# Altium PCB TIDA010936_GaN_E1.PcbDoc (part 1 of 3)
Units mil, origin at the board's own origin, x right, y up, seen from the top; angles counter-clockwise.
Board outline 2755.91 x 2708.83 mil, 4 copper layers (Top Layer, POWER, GND, Bottom Layer), stack 64.224 mil thick; 223 components, 99 nets, 571 pads, 439 vias.
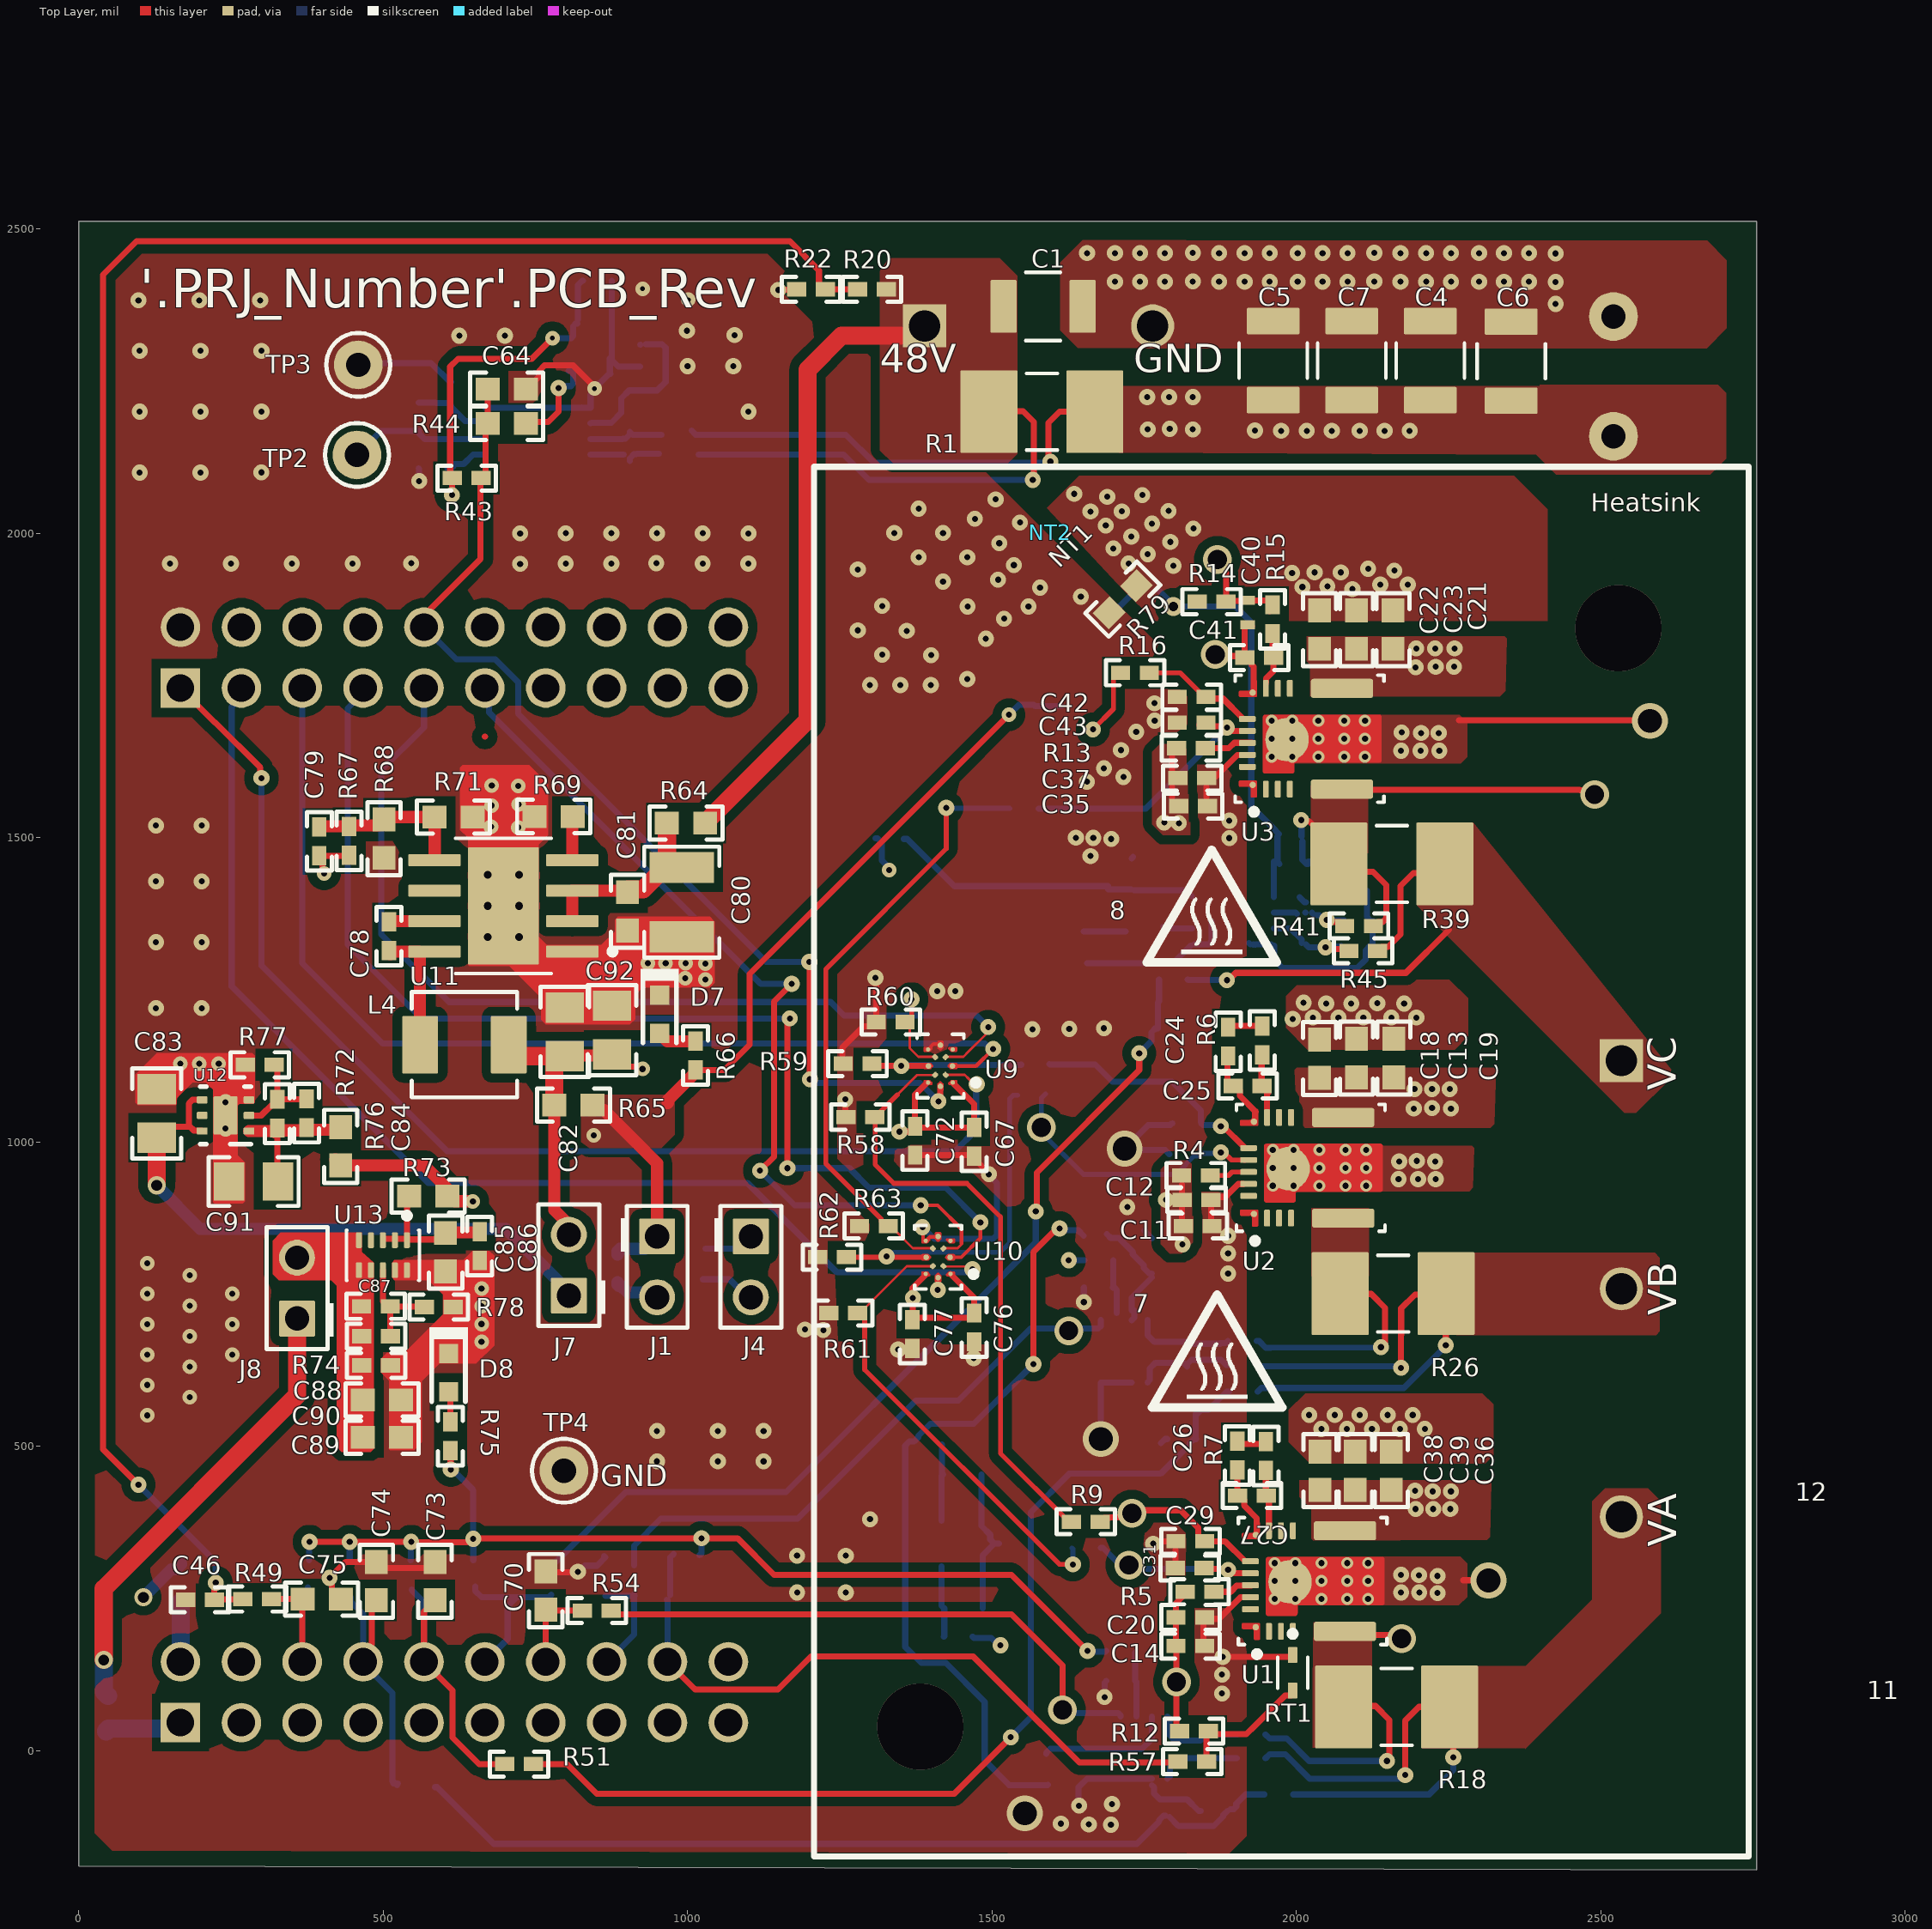
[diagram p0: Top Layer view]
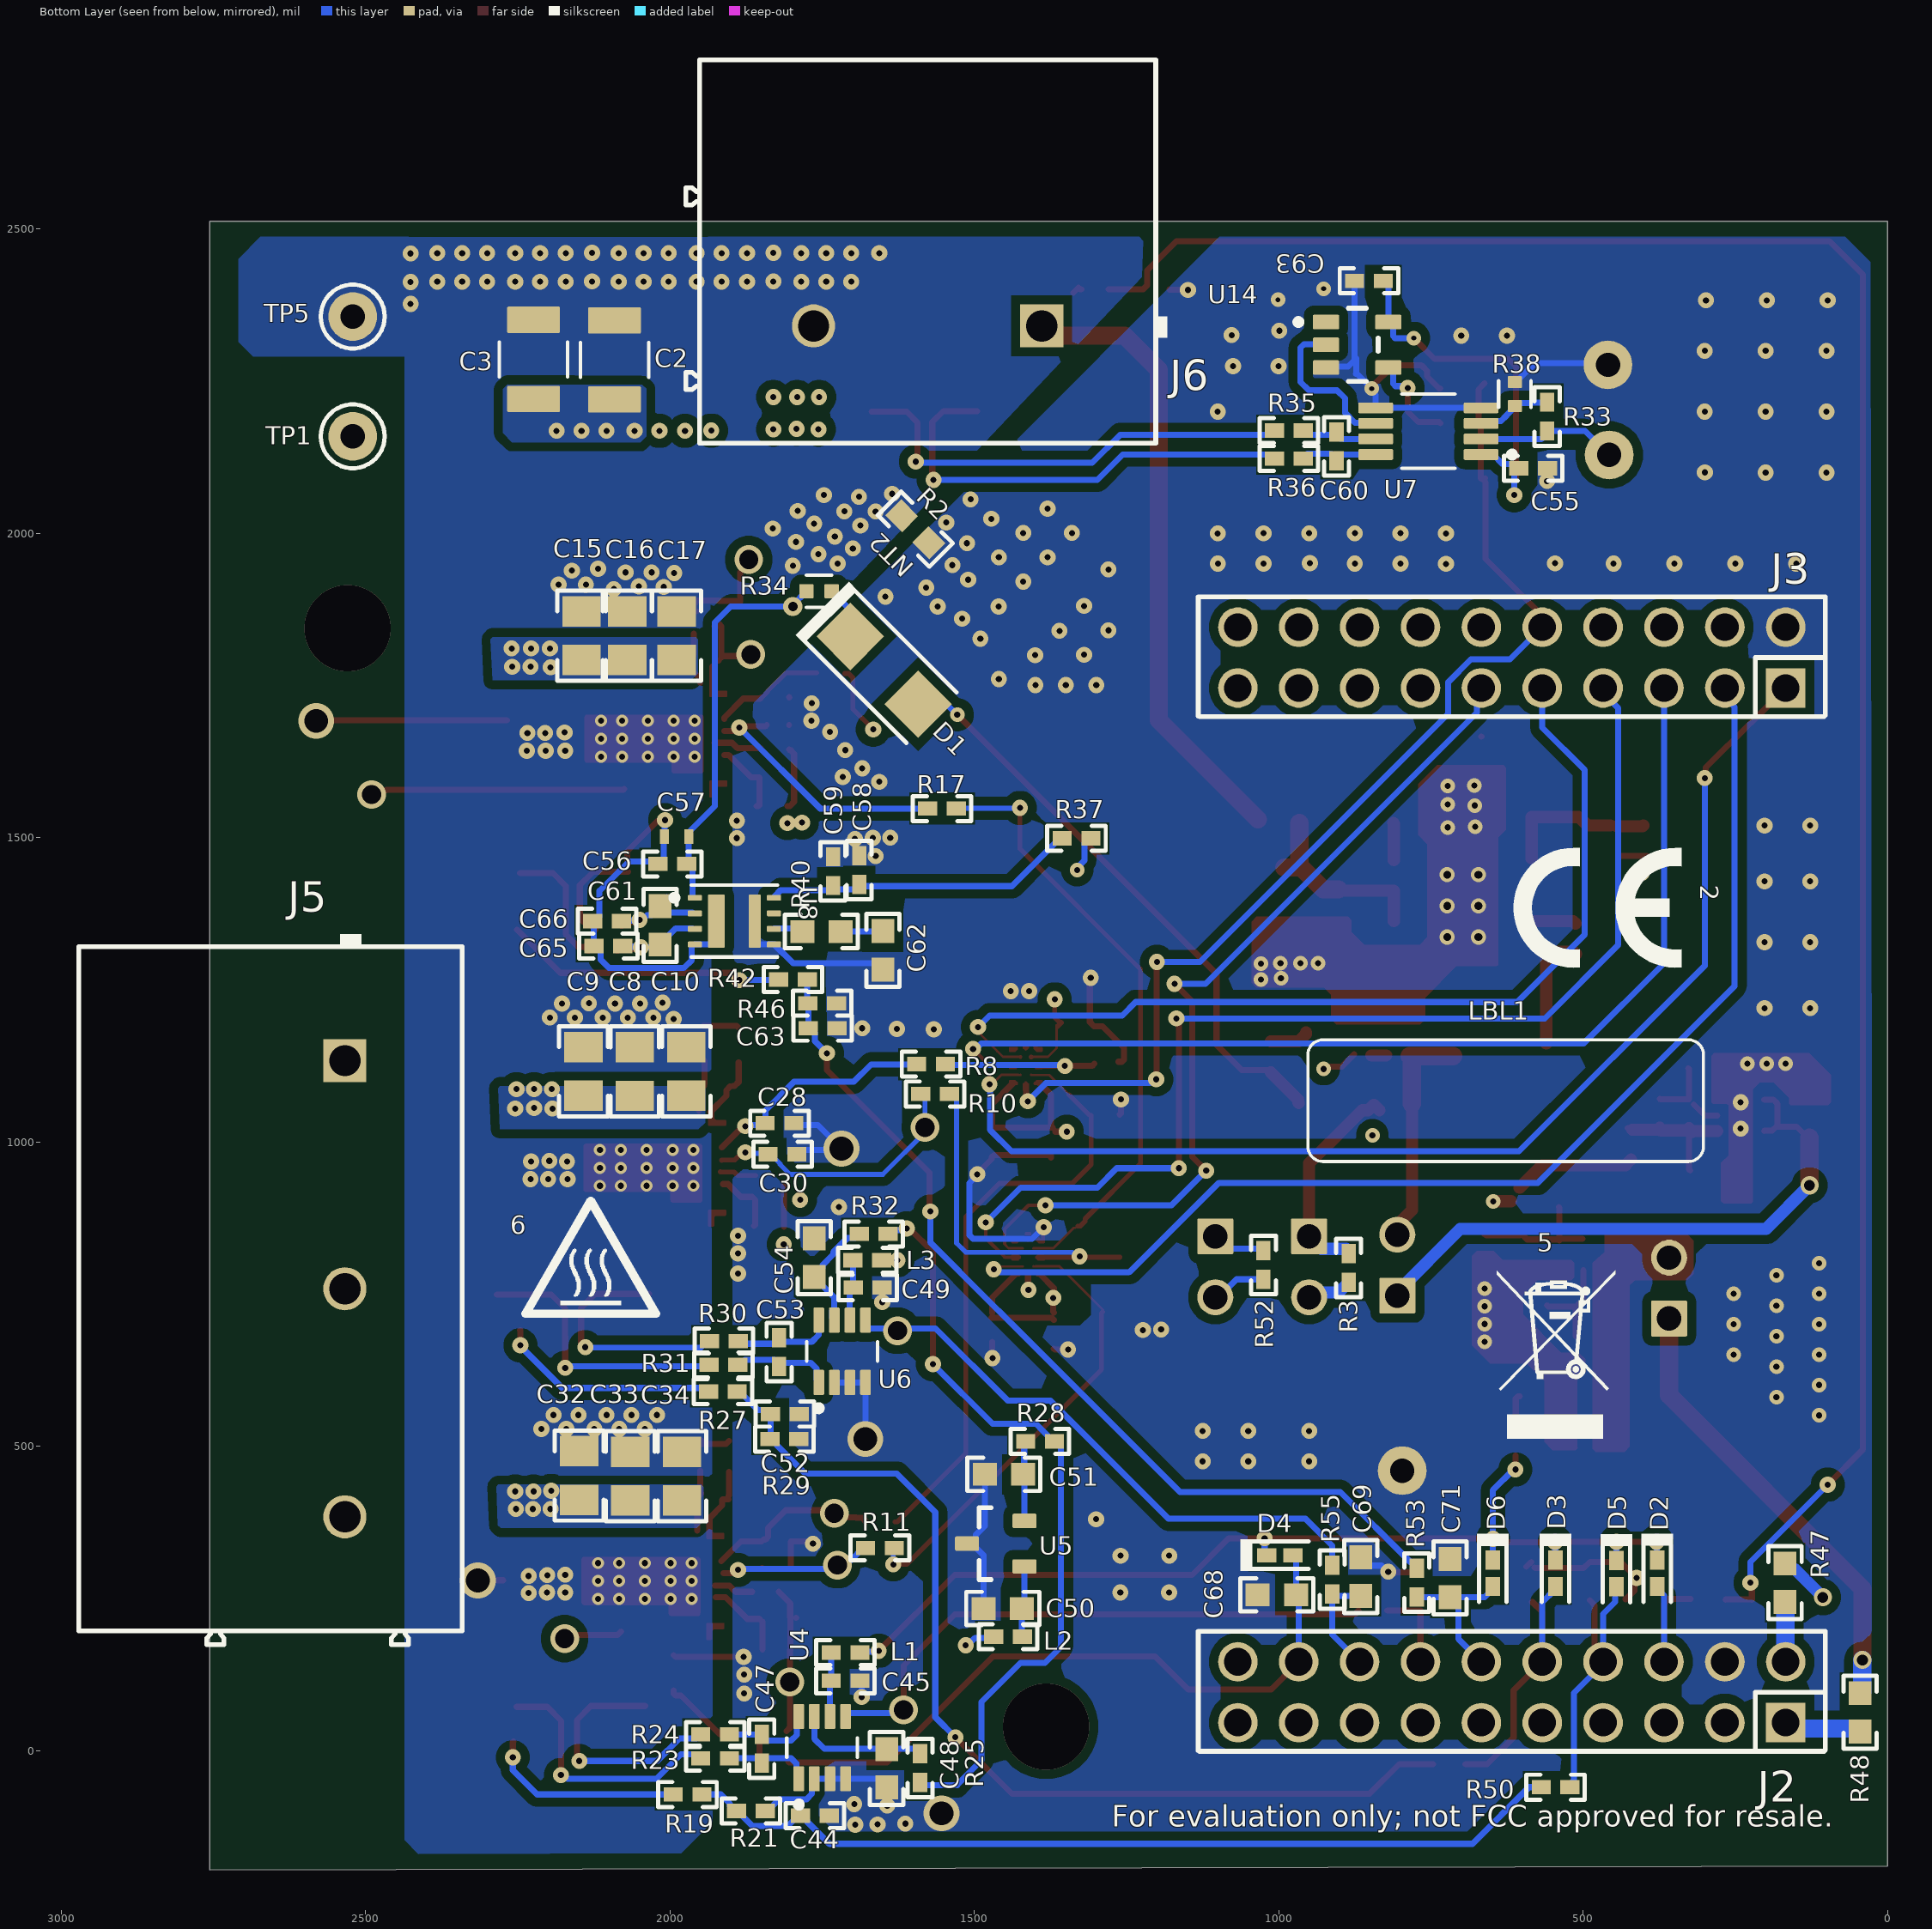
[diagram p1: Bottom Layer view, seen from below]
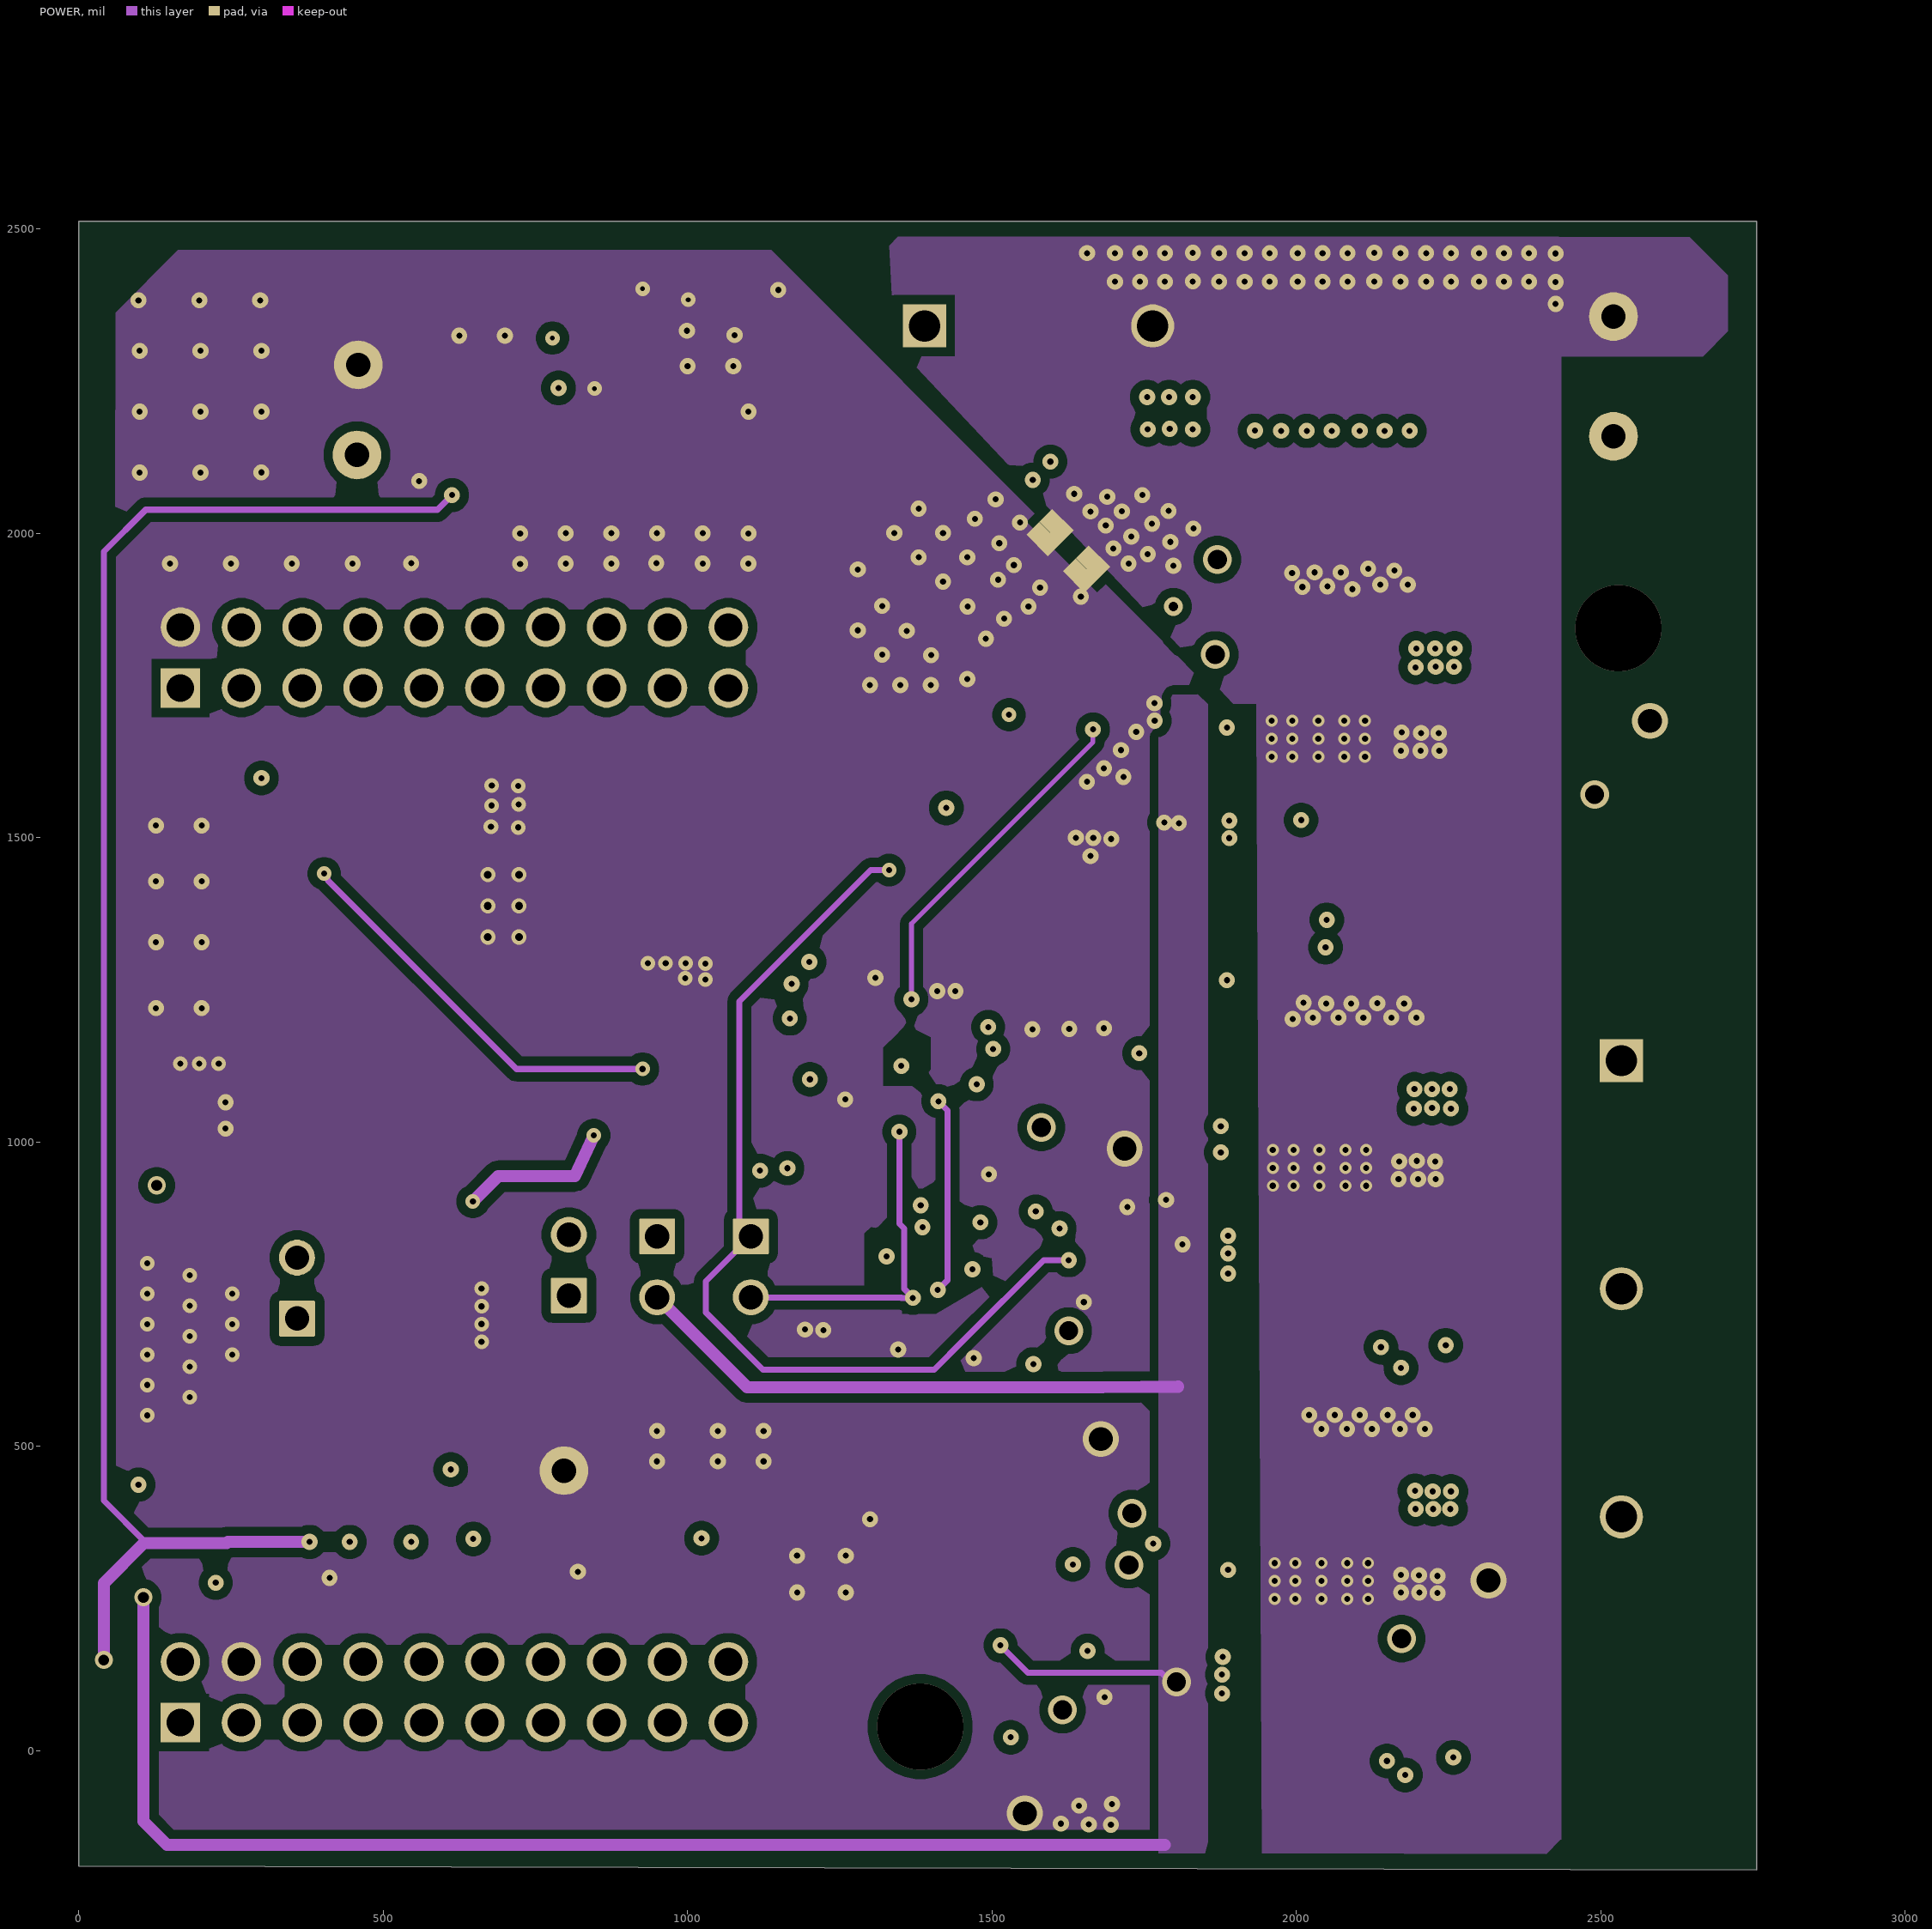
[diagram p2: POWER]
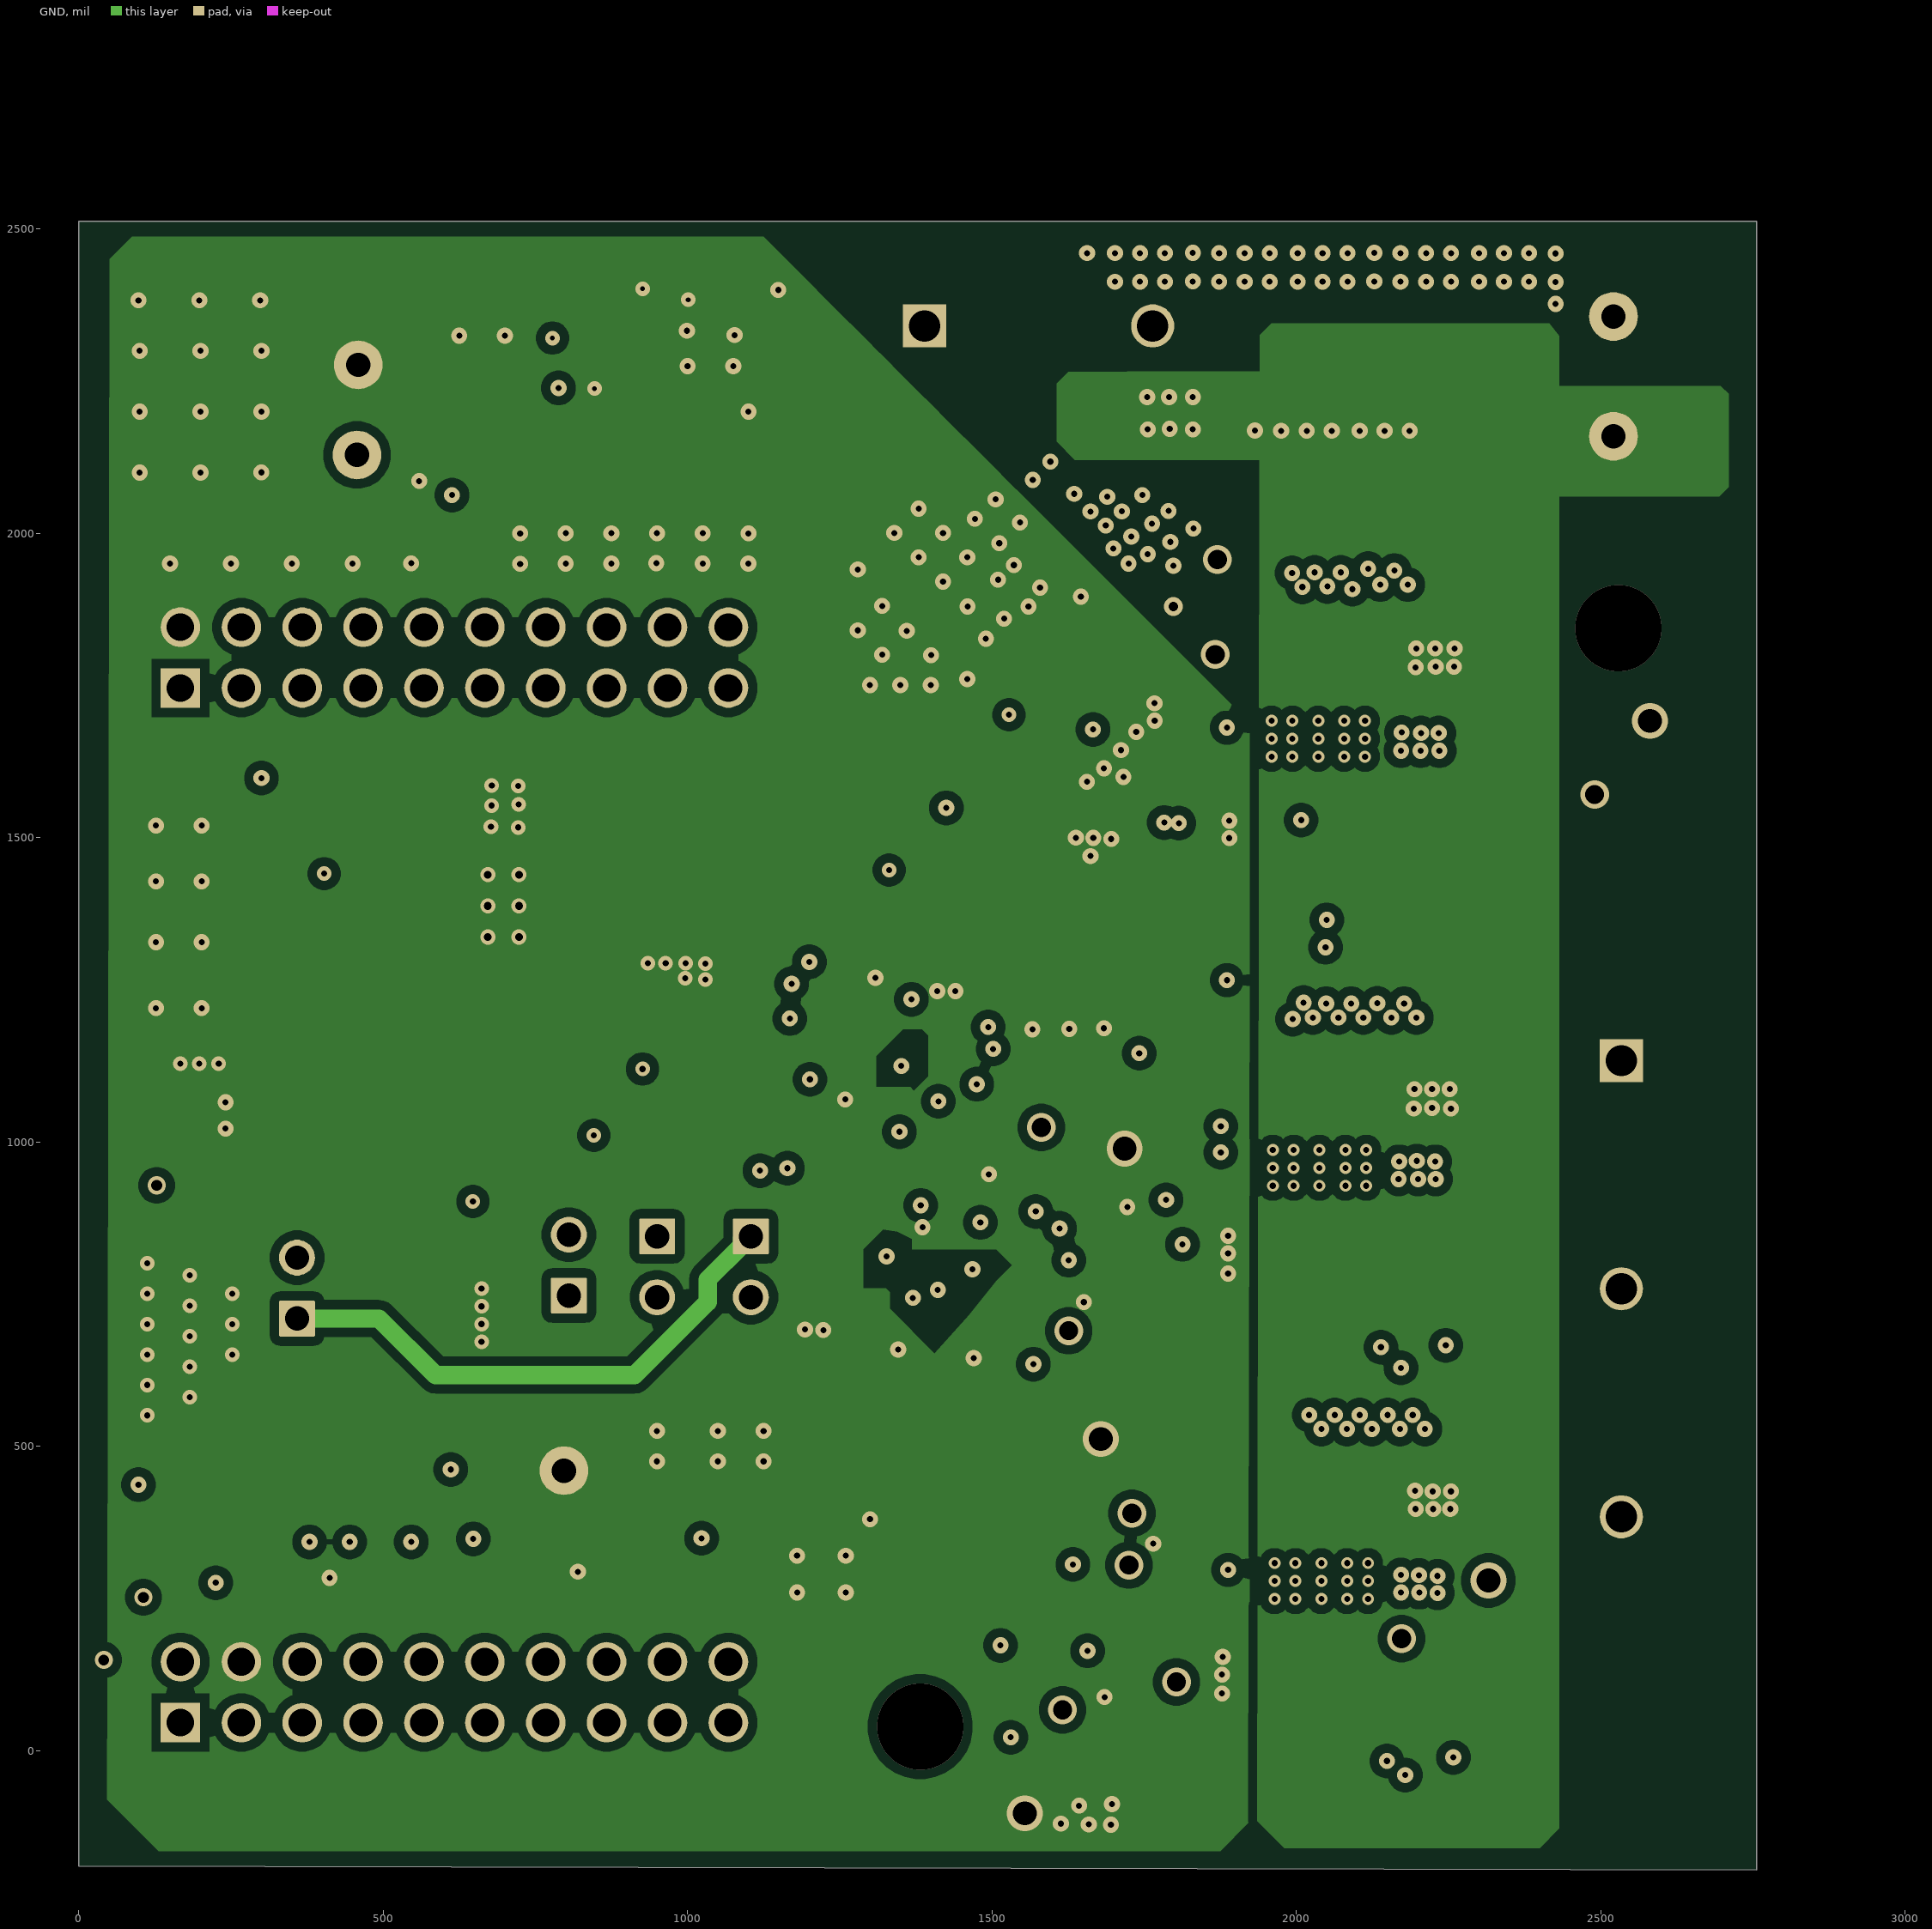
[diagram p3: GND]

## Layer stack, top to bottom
Top Solder: solder mask 0.4, Solder Resist, Dk 3.5
Top Layer: signal copper 2.7559
Dielectric 1: prepreg 8, FR-4 High Tg, Dk 4.2
POWER: signal copper 2.756
Dielectric 2: core 37.2, FR-4 High Tg, Dk 4.2
GND: signal copper 2.756
Dielectric 3: prepreg 8, FR-4 High Tg, Dk 4.2
Bottom Layer: signal copper 2.7559
Bottom Solder: solder mask 0.4, Solder Resist, Dk 3.5

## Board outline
0,-190 0,2512.83 2755.91,2512.83 2755.91,-196

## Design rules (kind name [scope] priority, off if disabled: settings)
AcuteAngle [All] p1: minimum=4.50000000000000E+0001 checktracksonly=FALSE
AssemblyTestPointUsage [All] p1: valid=2
BoardOutlineClearance BoardOutlineClearance_MountingHoles [OnCopper and InComponentClass('Mounting Holes')] p1: gap=40 ignorepadtopadclearanceinfootprint=FALSE
BoardOutlineClearance BoardOutlineClearance_Poly [OnCopper and InPoly] p2: gap=25 ignorepadtopadclearanceinfootprint=FALSE
BoardOutlineClearance [OnCopper and Not InComponentClass('Logo') and not InComponentClass('FiducialMark') and not InRegion(1000,500,4000,800)] p3: gap=25 ignorepadtopadclearanceinfootprint=FALSE
Clearance Clearance_Tie [WithinRoom('Tie')] p1: gap=0 ignorepadtopadclearanceinfootprint=FALSE
Clearance Clearance_PWM2 [WithinRoom('TIDA010936_Power')] p2: gap=0 ignorepadtopadclearanceinfootprint=FALSE
Clearance Clearance_PWM1 [WithinRoom('PWM1')] p3: gap=0 ignorepadtopadclearanceinfootprint=FALSE
Clearance Clearance_Keepouts [((IsTrack Or IsArc) And Not InPoly) And IsFree and IsKeepOut vs ((IsTrack Or IsArc) And Not InPoly) And IsFree and IsKeepOut] p4: gap=0 ignorepadtopadclearanceinfootprint=FALSE
Clearance Clearance_Poly [InPolygon] p5: gap=15 ignorepadtopadclearanceinfootprint=FALSE
Clearance [All] p6: gap=7.87 ignorepadtopadclearanceinfootprint=FALSE except(0: Arc-Text Arc-Hole Track-Text Track-Hole SMDPad-Text SMDPad-Hole THPad-Text THPad-Hole Via-Text Via-Hole Fill-Text Fill-Hole Poly-Text Poly-Hole Region-Text Region-Hole Text-Text Text-Hole)
ComponentClearance ComponentClearance_MountingHoles_FiducialMarks [InComponentClass('Mounting Holes') vs InComponentClass('FiducialMark')] p1: gap=50 collisioncheckmode=3 verticalgap=10 showdistances=FALSE
ComponentClearance ComponentClearance_Shunt [InComponentClass('Header') vs InComponentClass('Shunt')] p2: gap=0 collisioncheckmode=3 verticalgap=0 showdistances=FALSE
ComponentClearance ComponentClearance_Logo [InComponentClass('Logo')] p3: gap=50 collisioncheckmode=3 verticalgap=10 showdistances=FALSE
ComponentClearance ComponentClearance_ScrewToNut [(HasFootprint('NY PMS 440 0025 PH')) vs (HasFootprint('Keystone_1902C'))] p4: gap=5 collisioncheckmode=3 verticalgap=10 showdistances=FALSE
ComponentClearance ComponentClearance_MountingHoles [InComponentClass('Mounting Holes')] p5: gap=250 collisioncheckmode=3 verticalgap=100000 showdistances=FALSE
ComponentClearance ComponentClearance_SmallPassives [HasFootprint('0201*') or HasFootprint('0402*') or HasFootprint('0508') or HasFootprint('0603*') or HasFootprint('0612') or HasFootprint('0805*') or HasFootprint('0815*') or HasFootprint('0830*') or HasFootprint('1206*') or HasFootprint('1210*') or HasFootprint('1808*') or HasFootprint('1812*') or HasFootprint('1825*') or HasFootprint('2010*') or HasFootprint('2220*') or HasFootprint('2225*') or HasFootprint('2512*') or HasFootprint('2728*') or HasFootprint('3518*') vs HasFootprint('0201*') or HasFootprint('0402*') or HasFootprint('0508') or HasFootprint('0603*') or HasFootprint('0612') or HasFootprint('0805*') or HasFootprint('0815*') or HasFootprint('0830*') or HasFootprint('1206*') or HasFootprint('1210*') or HasFootprint('1808*') or HasFootprint('1812*') or HasFootprint('1825*') or HasFootprint('2010*') or HasFootprint('2220*') or HasFootprint('2225*') or HasFootprint('2512*') or HasFootprint('2728*') or HasFootprint('3518*')] p6: gap=14.96 collisioncheckmode=3 verticalgap=10 showdistances=FALSE
ComponentClearance ComponentClearance_THtoSMT [IsThruComponent vs IsSMTComponent] p7: gap=40 collisioncheckmode=3 verticalgap=30 showdistances=FALSE
ComponentClearance ComponentClearance_THtoTH [IsThruComponent vs IsThruComponent] p8: gap=30 collisioncheckmode=3 verticalgap=30 showdistances=FALSE
ComponentClearance [All] p9: gap=30 collisioncheckmode=3 verticalgap=10 showdistances=FALSE
DiffPairsRouting [All] p1: maxlimit=100 minlimit=10 mostfreqgap=10 toplayer_minwidth=15 toplayer_maxwidth=15 toplayer_prefwidth=15 midlayer1_minwidth=15 midlayer1_maxwidth=15 midlayer1_prefwidth=15 midlayer2_minwidth=15 midlayer2_maxwidth=15 midlayer2_prefwidth=15 bottomlayer_minwidth=15 bottomlayer_maxwidth=15 bottomlayer_prefwidth=15 maxuncoupledlength=1000
FabricationTestPointUsage TestPointUsage [All] p1: valid=2 allowmultiple=FALSE
FabricationTestpoint Testpoint [All] p1: side=3 testpointundercomponent=TRUE minsize=40 maxsize=100 preferedsize=60 minholesize=0 maxholesize=40 preferedholesize=32 testpointgrid=1 allowsidetop=TRUE allowsidebottom=TRUE usegrid=TRUE gridtolerance=0.01
FanoutControl Fanout_LCC [IsLCC] p1: bgadir=Out bgaviamode=Centered fanoutstyle=Auto fanoutdirection=Alternating viagrid=1 // Fanout_LCC (Default Rule)
FanoutControl Fanout_BGA [IsBGA] p2: bgadir=Out bgaviamode=Centered fanoutstyle=Auto fanoutdirection=Alternating viagrid=1 // Fanout_BGA (Default Rule)
FanoutControl Fanout_Default [All] p4: bgadir=Out bgaviamode=Centered fanoutstyle=Auto fanoutdirection=Alternating viagrid=1 // Fanout_Default (Default Rule)
FanoutControl Fanout_Small [(CompPinCount < 5)] p5: bgadir=Out bgaviamode=Centered fanoutstyle=Auto fanoutdirection=OutThenIn viagrid=1 // Fanout_Small (Default Rule)
HoleSize [All] p1: absolutevalues=TRUE maxlimit=251 minlimit=7.87 maxpercent=80.000 minpercent=20.000
MinimumAnnularRing MinimumAnnularRing_ThermalPadVias [IsVia and InAnyComponent] p1: minimumring=4.5
MinimumAnnularRing [All] p2: minimumring=4.5
MinimumSolderMaskSliver MinimumSolderMaskSliver_Logo [InComponentClass('Logo') vs InComponentClass('Logo')] p1: minsoldermaskwidth=0.7
MinimumSolderMaskSliver [All] p2: minsoldermaskwidth=2
PlaneClearance [All] p1: clearance=10
PlaneConnect [All] p1: planeconnectstyle=Relief reliefexpansion=10 reliefentries=4 reliefconductorwidth=10 reliefairgap=10
PolygonConnect [All] p1: connectstyle=Direct reliefconductorwidth=10 reliefentries=4 polygonreliefangle="90 Angle" airgapwidth=10
RoomDefinition TIDA010936_PoL_E1SchDoc [InComponentClass('TIDA010936_PoL_E1SchDoc')] p1: confinementstyle=ConfineIn formatcopy=TRUE lockcomponents=FALSE outline 1261,838 1476,838 1476,708 1261,708
RoomDefinition PWM1 [False] p2: confinementstyle=ConfineIn formatcopy=TRUE lockcomponents=FALSE outline 1335,1162 1462,1162 1462,1080 1335,1080
RoutingVias ThermalPadVias [IsVia and InAnyComponent] p1: holewidth=7.87 width=19.68 viastyle="Through Hole" minholewidth=7.87 minwidth=19.68 maxholewidth=12.99 maxwidth=26
RoutingVias [All] p2: holewidth=16 width=34 viastyle="Through Hole" minholewidth=6 minwidth=18 maxholewidth=40 maxwidth=65
SilkToBoardRegionClearance [Not ((IsComment or IsDesignator) And (Hide <> 'False')) and not InRegion(1000,500,4000,800)] p1:
SilkToSilkClearance SilkToSilkClearance_Pb-FreeLogo [(HasFootprint('Pb-Free_Overlay_Medium') OR HasFootprint('Pb-Free_Overlay_Small')) vs (HasFootprint('Pb-Free_Overlay_Medium') OR HasFootprint('Pb-Free_Overlay_Small'))] p1: silktosilkclearance=0
SilkToSilkClearance [All] p2: silktosilkclearance=0.1
SilkToSolderMaskClearance SilkToComponentPadClearance [IsPad and InAnycomponent] p1: minsilkscreentomaskgap=5 clearancetoexposedcopper=TRUE
SilkToSolderMaskClearance "Silk to Solder Mask Opening" [All] p2: minsilkscreentomaskgap=4 clearancetoexposedcopper=FALSE
SolderMaskExpansion [All] p1: expansion=1.97 istentingtop=FALSE
Width [All] p1: maxlimit=100 minlimit=4 preferedwidth=10 midlayer1_minwidth=6 midlayer2_minwidth=6 bottomlayer_minwidth=6 minimp=50.000000 maximp=50.000000 favimp=50.000000 checkconnectedcopper=TRUE
14 further rules are at their usual default settings.

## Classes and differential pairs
component class TIDA010936_Hardware_E1: 2 4 5 6 7 8 9 10 11 12 LBL1
component class TIDA010936_PoL_E1SchDoc: C78 C79 C80 C81 C82 C83 C84 C85 C86 C87 C88 C89 C90 C91 C92 D7 D8 J7 J8 L4 R64 R65 R66 R67 R68 R69 R71 R72 R73 R74 R75 R76 R77 R78 U11 U12 U13
component class Header: J1 J4 J7 J8
component class TIDA010936_Interface_E1: C67 C68 C69 C70 C71 C72 C73 C74 C75 C76 C77 D2 D3 D4 D5 D6 J2 J3 J4 J5 J6 R47 R48 R49 R50 R51 R52 R53 R54 R55 R57 R58 R59 R60 R61 R62 R63 TP4 TP5 U9 U10
component class TIDA010936_GaN_E1: C1 C2 C3 C4 C5 C6 C7 C8 C9 C10 C11 C12 C13 C14 C15 C16 C17 C18 C19 C20 C21 C22 C23 C24 C25 C26 C27 C28 C29 C30 C31 C32 C33 C34 C35 C36 C37 C38 C39 C40 C41 C42 C43 J1 NT1 NT2 R1 R2 R3 R4 R5 R6 R7 R8 R9 R10 R11 R12 R13 R14 R15 R16 R17 R79 RT1 TP1 U1 U2 U3
component class TIDA010936_Current_Sense_E1: C44 C45 C46 C47 C48 C49 C50 C51 C52 C53 C54 C55 C56 C57 C58 C59 C60 C61 C62 C63 C64 C65 C66 C93 D1 L1 L2 L3 R18 R19 R20 R21 R22 R23 R24 R25 R26 R27 R28 R29 R30 R31 R32 R33 R34 R35 R36 R37 R38 R39 R40 R41 R42 R43 R44 R45 R46 TP2 TP3 U4 U5 U6 U7 U8 U14
component class AssemblyNote: 9 10 11 12
component class Label: LBL1

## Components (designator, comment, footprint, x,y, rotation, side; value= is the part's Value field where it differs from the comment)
2 "CE Mark" CE_Mark_5mm 476,1385 r180 bottom
4 "FCC disclaimer" FCC_disclaimer 3530.43,5700.24 r90 top
5 "WEEE logo" WEEE_Minimum 546,685 r180 bottom
6 "CAUTION HOT SURFACE" IEC_HotSurface_Small 2130,811 r180 bottom
7 "CAUTION HOT SURFACE" IEC_HotSurface_Small 1870,657 r0 top
8 "CAUTION HOT SURFACE" IEC_HotSurface_Small 1861,1388 r0 top
9 "This Assembly Note is for PCB labels only" AssemblyNoteLabel 3237,38 r90 top
10 "These assemblies are ESD sensitive, ESD precautions shall be observed." AssemblyNote 3068,1591 r90 top
11 "These assemblies must be clean and free from flux and all contaminants. Use of no clean flux is not acceptable." AssemblyNote 2951,38 r90 top
12 "These assemblies must comply with workmanship standards IPC-A-610 Class 2, unless otherwise specified." AssemblyNote 2833,364 r90 top
C1 "C3225X7R2A106K250AC" FP-C3225X7R2A106K250AC_1210-MFG 1584,2373 r0 top value=10µF
C2 "C3225X7R2A106K250AC" FP-C3225X7R2A106K250AC_1210-MFG 2091,2285 r90 bottom value=10µF
C3 "C3225X7R2A106K250AC" FP-C3225X7R2A106K250AC_1210-MFG 2224,2286 r270 bottom value=10µF
C4 "C3225X7R2A106K250AC" FP-C3225X7R2A106K250AC_1210-MFG 2220,2284 r90 top value=10µF
C5 "C3225X7R2A106K250AC" FP-C3225X7R2A106K250AC_1210-MFG 1962,2284 r90 top value=10µF
C6 "C3225X7R2A106K250AC" FP-C3225X7R2A106K250AC_1210-MFG 2353,2283 r90 top value=10µF
C7 "C3225X7R2A106K250AC" FP-C3225X7R2A106K250AC_1210-MFG 2091,2284 r90 top value=10µF
C8 "C2012X7S2A105K125AE" 0805_HV 2057.73,1115.9 r90 bottom value=1uF
C9 "C2012X7S2A105K125AE" 0805_HV 2142,1116 r90 bottom value=1uF
C10 "C2012X7S2A105K125AE" 0805_HV 1973,1116 r90 bottom value=1uF
C11 "C1005X7S1A225K050BC" 0402_065 1838,862 r0 top value=2.2uF
C12 "CMP-0006351-2" 0402 1836,905 r180 top value=0.1uF
C13 "HMK107C7224KAHTE" 0603 2099,1138 r90 top value=0.22uF
C14 "C1005X7S1A225K050BC" 0402_065 1826,172 r0 top value=2.2uF
C15 "C2012X7S2A105K125AE" 0805_HV 2145,1832 r90 bottom value=1uF
C16 "C2012X7S2A105K125AE" 0805_HV 2070,1832 r90 bottom value=1uF
C17 "C2012X7S2A105K125AE" 0805_HV 1989,1832 r90 bottom value=1uF
C18 "HMK107C7224KAHTE" 0603 2038,1137 r90 top value=0.22uF
C19 "HMK107C7224KAHTE" 0603 2160,1138 r90 top value=0.22uF
C20 "CMP-0006351-2" 0402 1826,219 r0 top value=0.1uF
C21 "HMK107C7224KAHTE" 0603 2159,1842 r90 top value=0.22uF
C22 "HMK107C7224KAHTE" 0603 2038,1842 r90 top value=0.22uF
C23 "HMK107C7224KAHTE" 0603 2099,1842 r90 top value=0.22uF
C24 "CMP-0006351-2" 0402 1888,1165 r270 top value=0.1uF
C25 "CMP-0006351-2" 0402 1920,1092 r180 top value=0.1uF
C26 "CMP-0006351-2" 0402 1903,485 r270 top value=0.1uF
C27 "CMP-0006351-2" 0402 1927,419 r180 top value=0.1uF
C28 "CMP-0006388-2" 0402 1820,1031 r180 bottom value=47pF
C29 "CMP-0006388-2" 0402 1826,344 r180 top value=47pF
C30 "CMP-0006388-2" 0402 1815,980 r180 bottom value=47pF
C31 "CMP-0006388-2" 0402 1825,300 r180 top value=47pF
C32 "C2012X7S2A105K125AE" 0805_HV 2149,452 r90 bottom value=1uF
C33 "C2012X7S2A105K125AE" 0805_HV 2065,451 r90 bottom value=1uF
C34 "C2012X7S2A105K125AE" 0805_HV 1980,451 r90 bottom value=1uF
C35 "C1005X7S1A225K050BC" 0402_065 1830.38,1552 r0 top value=2.2uF
C36 "HMK107C7224KAHTE" 0603 2156,460 r90 top value=0.22uF
C37 "CMP-0006351-2" 0402 1829,1598 r180 top value=0.1uF
C38 "HMK107C7224KAHTE" 0603 2039,460 r90 top value=0.22uF
C39 "HMK107C7224KAHTE" 0603 2097,460 r90 top value=0.22uF
C40 "GRM155D81C475ME15D" 0402_070 1920,1870 r270 top value=4.7uF
C41 "CMP-0006351-2" 0402 1939,1796 r180 top value=0.1uF
C42 "CMP-0006388-2" 0402 1828.06,1731.35 r180 top value=47pF
C43 "CMP-0006388-2" 0402 1828.06,1689.25 r180 top value=47pF
C44 "CMP-0006632-2" 0402 1762,-107 r180 bottom value=0.033uF
C45 "CMP-0006351-2" 0402 1711.5,114.85 r0 bottom value=0.1uF
C46 "CMP-0006632-2" 0402 199,248 r180 top value=0.033uF
C47 "CMP-0006245-2" 0402 1849,3 r90 bottom value=1500pF
C48 "CMP-0007378-5" 0603 1644,-29 r90 bottom value=0.1uF
C49 "CMP-0006351-2" 0402 1675,761 r0 bottom value=0.1uF
C50 "GRM188R61A105KA61D" 0603 1453.27,233.75 r0 bottom value=1uF
C51 "CMP-0007378-5" 0603 1451.27,453.86 r180 bottom value=0.1uF
C52 "CMP-0006632-2" 0402 1811,553 r180 bottom value=0.033uF
C53 "CMP-0006245-2" 0402 1820.69,654.88 r90 bottom value=1500pF
C54 "CMP-0007378-5" 0603 1763,810 r270 bottom value=0.1uF
C55 "CMP-0006351-2" 0402 582,2107 r0 bottom value=0.1uF
C56 "CMP-0006351-2" 0402 1996,1457 r0 bottom value=0.1uF
C57 "GRM155D81C475ME15D" 0402_070 1989,1502 r0 bottom value=4.7uF
C58 "GRM155R61C225KE11D" 0402 1689,1447 r90 bottom value=2.2uF
C59 "CMP-0006351-2" 0402 1732,1445 r90 bottom value=0.1uF
C60 "CMP-0006245-2" 0402 905,2143 r270 bottom value=1500pF
C61 "C0603C472K5RACTU" 0603 2016,1356 r270 bottom value=4700pF
C62 "C0603C330J5GACTU" 0603 1650,1315 r270 bottom value=33pF
C63 "CMP-0006632-2" 0402 1749,1187 r180 bottom value=0.033uF
C64 "C0603C102F3GACTU" 0603 703,2237 r0 top value=1000pF
C65 "GRM155R72A471KA01D" 0402 2101,1322 r0 bottom value=470pF
C66 "GRM155R72A471KA01D" 0402 2103,1363 r0 bottom value=470pF
C67 "GRM155R71E104KE14D" 0402 1470.68,1000.24 r270 top value=0.1uF
C68 "CMP-0006827-4" 0603 1003,256 r0 bottom value=2200pF
C69 "CMP-0006827-4" 0603 865,286 r90 bottom value=2200pF
C70 "CMP-0006827-4" 0603 767,263 r90 top value=2200pF
C71 "CMP-0006827-4" 0603 718.16,283.6 r90 bottom value=2200pF
C72 "GRM155R71E104KE14D" 0402 1373.68,1002.24 r270 top value=0.1uF
C73 "CMP-0006827-4" 0603 585,278.5 r90 top value=2200pF
C74 "CMP-0006827-4" 0603 489,278.5 r90 top value=2200pF
C75 "CMP-0006827-4" 0603 399,249 r0 top value=2200pF
C76 "GRM155R71E104KE14D" 0402 1470.68,695.36 r90 top value=0.1uF
C77 "GRM155R71E104KE14D" 0402 1369.34,684.24 r270 top value=0.1uF
C78 "GRM155R71C104KA88D" 0402 509.49,1338.38 r90 top value=0.1uF
C79 "C1005C0G1H180J050BA" 0402 395,1494 r90 top value=18pF
C80 "C3225X7S2A475K200AE" 1210 990.49,1394.09 r270 top value=4.7uF
C81 "C1608X7S2A104K080AB" 0603 901.49,1379 r270 top value=0.1uF
C82 "C2012X6S1C156M125AC" 0805_HV 798.49,1181 r90 top value=15uF
C83 "C2012X7R1H225M125AC" 0805_HV 128,1047 r90 top value=2.2uF
C84 "CL05B103KB5NNNC" 0402 374,1047.38 r90 top value=0.01uF
C85 "JMK107BB7475MA-T" 0603 602.51,819 r270 top value=4.7uF
C86 "GCM155R71H471KA37D" 0402 658.51,829 r270 top value=470pF
C87 "GRM1555C1H121FA01D" 0402 487.89,730 r0 top value=120pF
C88 "GCM155R71H471KA37D" 0402 488.51,633 r0 top value=470pF
C89 "GRM188Z71A106MA73D" 0603 498.01,515 r0 top value=10uF
C90 "GRM188Z71A106MA73D" 0603 498.01,576 r0 top value=10uF
C91 "C2012X7R1H225M125AC" 0805_HV 287,935 r180 top value=2.2uF
C92 "C2012X6S1C156M125AC" 0805_HV 876,1184 r90 top value=15uF
C93 "CMP-0006351-2" 0402 851.62,2415 r0 bottom value=0.1uF
D1 "ES1C-13-F;  Superfast Rectifier, 150 V, 1 A" SMA 1648,1775 r225 bottom value=150V
D2 "CMP-0028644-3" SOD-523 378.16,291.46 r270 bottom value=70V
D3 "CMP-0028644-3" SOD-523 545.16,291.3 r270 bottom value=70V
D4 "CMP-0028644-3" SOD-523 998,321 r180 bottom value=70V
D5 "CMP-0028644-3" SOD-523 445,291 r270 bottom value=70V
D6 "CMP-0028644-3" SOD-523 648.16,291.32 r270 bottom value=70V
D7 "CMP-0002905-2" WL-SMCW_GREEN 954,1210 r270 top value=Green
D8 "CMP-0002905-2" WL-SMCW_GREEN 607.51,621 r270 top value=Green
J1 "CMP-0002337-1" CONN_PEC02SAAN 950,795 r270 top
J2 "CMP-0075442-1" CONN_SSW-110-23-F-D 617,96 r180 bottom locked
J3 "CMP-0075442-1" CONN_SSW-110-23-F-D 617,1796 r180 bottom locked
J4 "CMP-0002337-1" CONN_PEC02SAAN 1104,795 r270 top
J5 "600V, 30A" Phoenix_1904150 2656,759 r270 bottom
J6 "600V,30A" Phoenix_1902547 1576.6,2463.05 r0 bottom
J7 "CMP-0002337-1" CONN_PEC02SAAN 805,797.68 r90 top
J8 "CMP-0002337-1" CONN_PEC02SAAN 358.51,760 r90 top
L1 "CMP-0003227-1" 0402 1711.5,161.11 r0 bottom value="300 ohm"
L2 "CMP-0003227-1" 0402 1444.65,187.13 r0 bottom value="300 ohm"
L3 "CMP-0003227-1" 0402 1675.62,805.87 r0 bottom value="300 ohm"
L4 "74437324220" WE-LHMI_4020 633.49,1160 r0 top value=22uH
LBL1 "THT-14-423-10" Label_650x200 627,1068 r180 bottom
NT1 "CMP-0078142-6" Net-Tie_50milWide_30milLong 1655.39,1941.39 r225 top net-tie
NT2 "CMP-0078142-6" Net-Tie_50milWide_30milLong 1595.39,2001.39 r225 top net-tie
R1 "ULRG32512R001FLFSLT" FP-ULRG32512R001FLFSLT_2512-MFG 1582,2200 r0 top value=1m
R2 "CMP-0025883-3" 0603 1597,2007 r225 bottom value=0
R3 "CMP-0026822-3" 0402 885,793 r270 bottom value=0
R4 "CMP-0026822-3" 0402 1835,945 r180 top value=0
R5 "CMP-0026822-3" 0402 1841,261 r180 top value=0
R6 "CRCW04023R00JNED" 0402 1944,1167 r270 top value=3.0
R7 "CRCW04023R00JNED" 0402 1950,484 r270 top value=3.0
R8 "CMP-0026164-2" 0402 1571,1128 r180 bottom value=20.0
R9 "CMP-0026164-2" 0402 1654,376 r180 top value=20.0
R10 "CMP-0026164-2" 0402 1564.38,1079 r180 bottom value=20.0
R11 "CMP-0026164-2" 0402 1655,333 r180 bottom value=20.0
R12 "CMP-0026825-5" 0402 1832,32 r180 top value=10k
R13 "CMP-0026822-3" 0402 1827,1647 r180 top value=0
R14 "CMP-0026822-3" 0402 1861,1888 r180 top value=0
R15 "CRCW04023R00JNED" 0402 1961,1859 r270 top value=3.0
R16 "CMP-0026164-2" 0402 1735,1771 r180 top value=20.0
R17 "CMP-0026164-2" 0402 1553,1548 r180 bottom value=20.0
R18 "ULRG32512R001FLFSLT" FP-ULRG32512R001FLFSLT_2512-MFG 2164.76,71.88 r0 top value=1m
R19 "CMP-0025950-3" 0402 1971,-72 r0 bottom value=100k
R20 "CMP-0025950-3" 0402 1303,2401 r0 top value=100k
R21 "CMP-0026407-2" 0402 1867,-99 r0 bottom value=4.22k
R22 "CMP-0026407-2" 0402 1203,2401 r0 top value=4.22k
R23 "CMP-0026822-3" 0402 1925.73,-12.62 r0 bottom value=0
R24 "CMP-0026822-3" 0402 1925.73,26.62 r0 bottom value=0
R25 "CMP-0026822-3" 0402 1589,-28.55 r90 bottom value=0
R26 "ULRG32512R001FLFSLT" FP-ULRG32512R001FLFSLT_2512-MFG 2159,751 r0 top value=1m
R27 "CMP-0025950-3" 0402 1913,590 r0 bottom value=100k
R28 "CMP-0026822-3" 0402 1392,508 r180 bottom value=0
R29 "CMP-0026407-2" 0402 1812,512 r0 bottom value=4.22k
R30 "CMP-0026822-3" 0402 1911.16,672.97 r0 bottom value=0
R31 "CMP-0026822-3" 0402 1912.27,634 r0 bottom value=0
R32 "CMP-0026822-3" 0402 1665,849 r180 bottom value=0
R33 "CRCW040216K5FKED" 0402 559,2192 r270 bottom value=16.5k
R34 "RCC040210R0FKED" FP-RCC040210R0FKED_0402-MFG 1755,1905 r180 bottom value=10
R35 "CMP-0026822-3" 0402 983,2169 r0 bottom value=0
R36 "CMP-0026822-3" 0402 983,2123 r0 bottom value=0
R37 "CMP-0026822-3" 0402 1332,1499 r180 bottom value=0
R38 "RMCF0402FT11K0" FP-RMCF0402FT11K0_0402-MFG 612,2229 r90 bottom value=11k
R39 "ULRG32512R001FLFSLT" FP-ULRG32512R001FLFSLT_2512-MFG 2157,1457 r0 top value=1m
R40 "CRCW060350R0FKEA" 0603 1751,1346 r0 bottom value=50
R41 "ERJ-2GEJ220X" 0402 2103,1355 r0 top value=22
R42 "CMP-0025950-3" 0402 1798,1267 r0 bottom value=100k
R43 "CMP-0026825-5" 0402 637,2091 r180 top value=10k
R44 "RC0603JR-071KL" 0603 703,2181 r180 top value=1.0k
R45 "ERJ-2GEJ220X" 0402 2110,1314 r0 top value=22
R46 "CMP-0026407-2" 0402 1750,1228 r0 bottom value=4.22k
R47 "PMR03EZPJ000" 0603 168,276 r270 bottom value=0
R48 "PMR03EZPJ000" 0603 45,63 r90 bottom value=0
R49 "CMP-0026876-3" 0402 293,249 r0 top value=20
R50 "CMP-0026876-3" 0402 545,-60 r180 bottom value=20
R51 "CMP-0026876-3" 0402 723,-22 r180 top value=20
R52 "CMP-0026822-3" 0402 1025,798 r90 bottom value=0
R53 "CMP-0026876-3" 0402 773.16,276 r270 bottom value=20
R54 "CMP-0026876-3" 0402 851,230 r180 top value=20
R55 "CMP-0026876-3" 0402 912,281 r270 bottom value=20
R57 "CMP-0026876-3" 0402 1829,-18 r180 top value=20
R58 "CMP-0026825-5" 0402 1284,1041 r0 top value=10k
R59 "CMP-0026825-5" 0402 1279.27,1128.63 r0 top value=10k
R60 "CMP-0026825-5" 0402 1333.7,1197.05 r0 top value=10k
R61 "CMP-0026825-5" 0402 1255.64,718.98 r0 top value=10k
R62 "CMP-0026825-5" 0402 1237.25,810.98 r0 top value=10k
R63 "CMP-0026825-5" 0402 1306,862 r0 top value=10k
R64 "PMR03EZPJ000" 0603 997.49,1524 r0 top value=0
R65 "PMR03EZPJ000" 0603 812.49,1061 r180 top value=0
R66 "CMP-0026854-5" 0402 1013,1142 r90 top value=1.2k
R67 "CRCW040240K2FKED" 0402 444,1495 r270 top value=40.2k
R68 "CRCW060382K5FKEA" 0603 501.49,1498.5 r90 top value=82.5k
R69 "CRCW060342K2FKEA" 0603 779.99,1535 r0 top value=42.2k
R71 "M55342K12B10E0T" 0603 615.49,1534 r180 top value=10.0k
R72 "PMR03EZPJ000" 0603 430,993 r90 top value=0
R73 "PMR03EZPJ000" 0603 574,911 r0 top value=0
R74 "CRCW0402115KFKED" 0402 488.13,681 r180 top value=115k
R75 "CMP-0026979-3" 0402 610.51,516.62 r270 top value=820
R76 "CRCW0402174KFKED" 0402 326,1046.62 r270 top value=174k
R77 "CRCW040221K5FKED" 0402 297,1127 r0 top value=21.5k
R78 "CRCW040225K5FKED" 0402 591.13,729 r180 top value=25.5k
R79 "CMP-0025883-3" 0603 1715,1892 r225 top value=0
RT1 "TMP6131DYAT" DYA0002A-MFG 1994,128 r270 top value=10k
TP1 "5000" Keystone5000 2521,2159.57 r90 bottom locked
TP2 "5000" Keystone5000 457,2129 r90 top
TP3 "CMP-0055138-2" Keystone5001 459,2277 r90 top
TP4 "CMP-0055138-2" Keystone5001 797,460 r90 top
TP5 "CMP-0055138-2" Keystone5001 2521,2356.43 r90 bottom locked
U1 "LMG2100R044" RAR0016A-MFG 2026.86,278.65 r90 top locked
U2 "LMG2100R044" RAR0016A-MFG 2023.86,957.65 r90 top locked
U3 "LMG2100R044" RAR0016A-MFG 2021.86,1662.65 r90 top locked
U4 "INA241A3IDDF" DDF0008A-MFG 1749.89,4.92 r90 bottom
U5 "REF3333AIDBZR" DBZ0003A_N 1464.65,340.13 r0 bottom
U6 "INA241A3IDDF" DDF0008A-MFG 1717.05,656.18 r90 bottom
U7 "INA310A2IDGKR" DGK0008A-MFG 754,2168 r0 bottom
U8 "AMC0106DENR" DEN0008A-MFG-NO_VIA 1894,1363 r180 bottom
U9 "TXU0304DTR" DTR0012A-MFG 1415.35,1125 r180 top
U10 "TXU0304DTR" DTR0012A-MFG 1411.61,810.59 r180 top
U11 "LMR38010FDDAR" DDA0008E-MFG 697.49,1388 r180 top
U12 "TPS74601PDRVR" DRV0006A 241,1043.72 r180 top
U13 "TPSM82821ASILR" SIL0010D-MFG 499.51,814 r270 top
U14 "SN74LVC1G14DBVT" FP-DBV0005A-MFG 871,2310 r180 bottom

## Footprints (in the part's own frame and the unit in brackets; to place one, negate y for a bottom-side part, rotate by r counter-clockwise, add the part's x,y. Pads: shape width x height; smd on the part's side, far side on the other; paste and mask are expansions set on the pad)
0402 [mm] "0402 from SM-752 data"
  rect 0.8x0.6 smd: 1(-0.6,0) 2(0.6,0)
  silkscreen extent -1.22,-0.52 1.22,0.52, body extent -0.55,-0.3 0.55,0.3, height 0.6
0402_065 [mm] "0402"
  rect 0.8x0.6 smd: 1(-0.6,0) 2(0.6,0)
  silkscreen extent -1.22,-0.52 1.22,0.52, body extent -0.55,-0.3 0.55,0.3, height 0.65
0402_070 [mil] "SMD, 2-Leads, Body 1.2x0.7mm, Height 0.7mm"
  rect 15x24 smd: 1(-20,0) 2(20,0)
  body extent -24,-14 24,14, height 28
0603 [mm] "0603 from SM-752 data"
  rect 1x0.95 smd: 1(-0.8,0) 2(0.8,0)
  silkscreen extent -1.52,-0.69 1.52,0.69, body extent -0.87,-0.47 0.87,0.47, height 1
0805_HV [mil] "0805 with 30mil clearance between pads"
  rect 50x63 smd: 1(-40,0) 2(40,0)
  silkscreen extent -74,-40 74,40, body extent -43,-29 43,29, height 57
1210 [mm] "1210 from SM-752 data"
  rect 1.3x2.7 smd: 1(-1.45,0) 2(1.45,0)
  silkscreen extent -2.32,-1.57 2.32,1.57, body extent -1.7,-1.35 1.7,1.35, height 1.35
AssemblyNote [mil] "Assembly Note"
AssemblyNoteLabel [mil] "Assembly Note for PCB Labels"
CE_Mark_5mm [mil] "Minimum text height for CE Mark"
  silkscreen extent -138,-98 138,98
CONN_PEC02SAAN [mm] "SULLINS"
  rrect7% 1.5x1.5 hole 1.016: 1(-1.27,0)
  round 1.5 hole 1.016: 2(1.27,0)
  silkscreen extent -2.54,-1.52 2.54,1.27, body extent -2.54,-1.27 2.54,1.27, height 8.38
CONN_SSW-110-23-F-D [mm] "SAMTEC"
  rect 1.65x1.65 hole 1.15: 1(11.43,-1.27)
  round 1.65 hole 1.15: 2(11.43,1.27) 3(8.89,-1.27) 4(8.89,1.27) 5(6.35,-1.27) 6(6.35,1.27) 7(3.81,-1.27) 8(3.81,1.27) 9(1.27,-1.27) 10(1.27,1.27) 11(-1.27,-1.27) 12(-1.27,1.27) 13(-3.81,-1.27) 14(-3.81,1.27) 15(-6.35,-1.27) 16(-6.35,1.27) 17(-8.89,-1.27) 18(-8.89,1.27) 19(-11.43,-1.27) 20(-11.43,1.27)
  silkscreen extent -13.08,-2.46 13.08,2.54, body extent -13,-2.51 13,2.54, height 8.59
DBZ0003A_N [mm] "SOT23, 3-Leads, Body 2.9x1.3mm, Pitch 0.95mm, Lead Span 2.4mm, IPC Medium Density"
  rrect17% 1x0.6 smd: 1(-1.2,0.95) 2(-1.2,-0.95) 3(1.2,0)
  silkscreen extent 0.2,-1.5 0.7,1.5, body extent -1.26,-1.46 1.26,1.46, height 0.98
DDA0008E-MFG [mm]
  rrect20% 2.2x0.5 smd paste-1000 mask+0: 1(-2.875,1.905) 2(-2.875,0.635) 3(-2.875,-0.635) 4(-2.875,-1.905) 5(2.875,-1.905) 6(2.875,-0.635) 7(2.875,0.635) 8(2.875,1.905)
  rrect3% 2.95x4.9 smd paste-1000 mask-1000: 9(0,0)
  silkscreen extent -4.68,-2.83 2,2.83, body extent -4.08,-2.68 4.08,2.68, height 0.25
DDF0008A-MFG [mm]
  rrect22% 1.05x0.45 smd paste+0 mask+0: 1(-1.3,0.975) 2(-1.3,0.325) 3(-1.3,-0.325) 4(-1.3,-0.975) 5(1.3,-0.975) 6(1.3,-0.325) 7(1.3,0.325) 8(1.3,0.975)
  silkscreen extent -2.5,-1.48 0.4,1.48, body extent -1.41,-1.45 1.41,1.45, height 1.1
DEN0008A-MFG-NO_VIA [mm]
  rrect40% 0.6x0.25 smd paste+0 mask+0: 1(-1.65,0.975) 2(-1.65,0.325) 3(-1.65,-0.325) 4(-1.65,-0.975) 5(1.65,-0.975) 6(1.65,-0.325) 7(1.65,0.325) 8(1.65,0.975)
  rrect14% 0.7x2.23 smd paste-1000 mask+0: 4(-0.75,0)
  rrect20% 0.5x2.23 smd paste-1000 mask+0: 5(0.85,0)
  silkscreen extent -2.63,-1.5 1.8,1.5, body extent -1.75,-1.35 1.75,1.35, height 1
DGK0008A-MFG [mm]
  rrect22% 1.45x0.45 smd paste+0 mask+0: 1(-2.2,0.975) 2(-2.2,0.325) 3(-2.2,-0.325) 4(-2.2,-0.975) 5(2.2,-0.975) 6(2.2,-0.325) 7(2.2,0.325) 8(2.2,0.975)
  silkscreen extent -3.61,-1.55 1.1,1.55, body extent -2.45,-1.5 2.45,1.5, height 1.1
DRV0006A [mm] "SON, 6-Leads, Body 2x2mm, Pitch 0.65mm, Thermal Pad 1.6x1mm, TI Recommended"
  rrect33% 0.45x0.3 smd: 1(-0.975,0.65) 2(-0.975,0) 3(-0.975,-0.65) 4(0.975,-0.65) 5(0.975,0) 6(0.975,0.65)
  rrect14% 1x0.7 on Top Paste: 7(0,0.45) 7(0,-0.45)
  rrect10% 1x1.6 smd paste-0.5: 7(0,0)
  silkscreen extent -1.05,-1.2 1.05,1.2, body extent -1.05,-1.05 1.05,1.05, height 0.81
DTR0012A-MFG [mm]
  round 0.18 smd paste-1000 mask+0: 1(-0.515,0.69) 5(-0.515,-0.69) 7(0.515,-0.69) 11(0.515,0.69)
  rrect50% 0.23x0.2 smd rot 135 paste+0 mask+0: 2(-0.22,0.37) 8(0.22,-0.37)
  round 0.234 smd paste-1000 mask+0: 3(-0.5,0) 6(0,-0.868) 9(0.5,0) 12(0,0.85)
  rrect50% 0.23x0.2 smd rot 45 paste+0 mask+0: 4(-0.22,-0.37) 10(0.22,0.37)
  Top Layer region: -0.7,0.74 -0.693,0.765 -0.675,0.783 -0.65,0.79 -0.65,0.79 -0.38,0.79 -0.361,0.786 -0.345,0.775 -0.334,0.759 -0.33,0.74 -0.33,0.74 -0.33,0.726 -0.334,0.707 -0.345,0.691 -0.345,0.691 -0.431,0.605 -0.447,0.594 -0.466,0.59 -0.466,0.59 -0.65,0.59 -0.669,0.594 -0.685,0.605 -0.696,0.621 -0.7,0.64 -0.7,0.64
  Top Layer region: -0.7,-0.74 -0.693,-0.765 -0.675,-0.783 -0.65,-0.79 -0.65,-0.79 -0.38,-0.79 -0.361,-0.786 -0.345,-0.775 -0.334,-0.759 -0.33,-0.74 -0.33,-0.74 -0.33,-0.726 -0.334,-0.707 -0.345,-0.691 -0.345,-0.691 -0.431,-0.605 -0.447,-0.594 -0.466,-0.59 -0.466,-0.59 -0.65,-0.59 -0.669,-0.594 -0.685,-0.605 -0.696,-0.621 -0.7,-0.64 -0.7,-0.64
  Top Layer region: 0.7,-0.74 0.693,-0.765 0.675,-0.783 0.65,-0.79 0.65,-0.79 0.38,-0.79 0.361,-0.786 0.345,-0.775 0.334,-0.759 0.33,-0.74 0.33,-0.74 0.33,-0.726 0.334,-0.707 0.345,-0.691 0.345,-0.691 0.431,-0.605 0.447,-0.594 0.466,-0.59 0.466,-0.59 0.65,-0.59 0.669,-0.594 0.685,-0.605 0.696,-0.621 0.7,-0.64 0.7,-0.64
  Top Layer region: 0.7,0.74 0.693,0.765 0.675,0.783 0.65,0.79 0.65,0.79 0.38,0.79 0.361,0.786 0.345,0.775 0.334,0.759 0.33,0.74 0.33,0.74 0.33,0.726 0.334,0.707 0.345,0.691 0.345,0.691 0.431,0.605 0.447,0.594 0.466,0.59 0.466,0.59 0.65,0.59 0.669,0.594 0.685,0.605 0.696,0.621 0.7,0.64 0.7,0.64
  Top Layer region: -0.7,0.08 -0.696,0.099 -0.685,0.115 -0.669,0.126 -0.65,0.13 -0.65,0.13 -0.425,0.13 -0.406,0.126 -0.39,0.115 -0.39,0.115 -0.315,0.04 -0.304,0.024 -0.3,0.005 -0.3,0.005 -0.3,-0.005 -0.304,-0.024 -0.315,-0.04 -0.315,-0.04 -0.39,-0.115 -0.406,-0.126 -0.425,-0.13 -0.425,-0.13 -0.65,-0.13 -0.675,-0.123 -0.693,-0.105 -0.7,-0.08 -0.7,-0.08
  Top Layer region: 0.7,0.08 0.696,0.099 0.685,0.115 0.669,0.126 0.65,0.13 0.65,0.13 0.425,0.13 0.406,0.126 0.39,0.115 0.39,0.115 0.315,0.04 0.304,0.024 0.3,0.005 0.3,0.005 0.3,-0.005 0.304,-0.024 0.315,-0.04 0.315,-0.04 0.39,-0.115 0.406,-0.126 0.425,-0.13 0.425,-0.13 0.65,-0.13 0.675,-0.123 0.693,-0.105 0.7,-0.08 0.7,-0.08
  Top Layer region: 0.08,1.05 0.099,1.046 0.115,1.035 0.126,1.019 0.13,1 0.13,1 0.13,0.775 0.126,0.756 0.115,0.74 0.115,0.74 0.04,0.665 0.024,0.654 0.005,0.65 0.005,0.65 -0.005,0.65 -0.024,0.654 -0.04,0.665 -0.04,0.665 -0.115,0.74 -0.126,0.756 -0.13,0.775 -0.13,0.775 -0.13,1 -0.123,1.025 -0.105,1.043 -0.08,1.05 -0.08,1.05
  Top Layer region: 0.08,-1.05 0.099,-1.046 0.115,-1.035 0.126,-1.019 0.13,-1 0.13,-1 0.13,-0.775 0.126,-0.756 0.115,-0.74 0.115,-0.74 0.04,-0.665 0.024,-0.654 0.005,-0.65 0.005,-0.65 -0.005,-0.65 -0.024,-0.654 -0.04,-0.665 -0.04,-0.665 -0.115,-0.74 -0.126,-0.756 -0.13,-0.775 -0.13,-0.775 -0.13,-1 -0.123,-1.025 -0.105,-1.043 -0.08,-1.05 -0.08,-1.05
  silkscreen extent -1.6,-1.33 0.97,1.33, body extent -0.8,-1.15 0.8,1.15, height 0.25
DYA0002A-MFG [mm]
  rrect25% 0.67x0.4 smd paste+0 mask+0: 1(-0.74,0) 2(0.74,0)
  silkscreen extent -1.75,-0.63 0.65,0.63, body extent -1.17,-0.67 1.17,0.67, height 0.25
FCC_disclaimer [mil]
FP-C3225X7R2A106K250AC_1210-MFG [mm]
  rrect9% 1.1x2.2 smd paste+0 mask+0: 1(-1.65,0) 2(1.65,0)
  silkscreen extent -0.72,-1.43 0.72,1.43, body extent -1.6,-1.25 1.6,1.25, height 2.85
FP-DBV0005A-MFG [mm]
  rrect17% 1.1x0.6 smd paste+0 mask+0: 1(-1.3,0.95) 2(-1.3,0) 3(-1.3,-0.95) 4(1.3,-0.95) 5(1.3,0.95)
  silkscreen extent -2.58,-1.53 0.87,1.53, body extent -1.4,-1.45 1.4,1.45, height 1.45
FP-RCC040210R0FKED_0402-MFG [mm]
  rrect17% 0.6x0.6 smd paste+0 mask+0: 1(-0.525,0) 2(0.525,0)
  silkscreen extent -0.53,-0.67 0.53,0.67, body extent -0.5,-0.25 0.5,0.25, height 0.4
FP-RMCF0402FT11K0_0402-MFG [mm]
  rrect20% 0.5x0.6 smd paste+0 mask+0: 1(-0.5,0) 2(0.5,0)
  silkscreen extent -0.55,-0.67 0.55,0.67, body extent -0.5,-0.25 0.5,0.25, height 0.4
FP-ULRG32512R001FLFSLT_2512-MFG [mm]
  rrect4% 2.38x3.45 smd paste+0 mask+0: 1(-2.21,0) 2(2.21,0)
  silkscreen extent -0.64,-1.6 0.64,1.6, body extent -3.5,-1.83 3.5,1.83, height 0.25
IEC_HotSurface_Small [mil]
  silkscreen extent -107,-93 107,92
Keystone5000 [mil] "For Keystone 500x miniature loop terminals"
  round 80 hole 40: 1(0,0)
  silkscreen extent -52,-52 52,52, body extent -49,-49 49,49, height 182
Keystone5001 [mil] "For Keystone 500x miniature loop terminals"
  round 80 hole 40: 1(0,0)
  silkscreen extent -52,-52 52,52, body extent -49,-49 49,49, height 182
Label_650x200 [mil] "Thermal Transfer Label"
  round 1 on Mech14: 0(0,0)
  silkscreen extent -325,-100 325,100, body extent -325,-100 325,100, height 1
Net-Tie_50milWide_30milLong [mil] "50mil net tie, no solder mask opening, no solder paste"
  rect 30x50 on Mid1 paste-20 mask-20: 1(-15,0) 2(15,0)
Phoenix_1902547 [mm] "TH, 2-Leads, Body 19.04x16mm, Pitch 9.52mm"
  rect 1.8x1.8 hole 1.3: 1(-4.76,3.1)
  round 1.8 hole 1.3: 2(4.76,3.1)
  silkscreen extent -10,-8 10.09,8, body extent -9.52,-8 10.09,8, height 22
Phoenix_1904150 [mm] "TH, 3-Leads, Body 28.56x16mm, Pitch 9.52mm"
  rect 1.8x1.8 hole 1.3: 1(-9.52,3.1)
  round 1.8 hole 1.3: 2(0,3.1) 3(9.52,3.1)
  silkscreen extent -14.8,-8 14.85,8, body extent -14.28,-8 14.85,8, height 22
RAR0016A-MFG [mm]
  round 0.265 smd paste+0 mask-1000: 1(-1.925,2.375) 11(1.925,2.375)
  rrect40% 0.7x0.25 smd paste+0 mask-1000: 2(-2.1,1.825) 3(-2.1,1.325) 4(-2.1,0.825) 8(2.1,0.825) 9(2.1,1.325) 10(2.1,1.825)
  rrect25% 0.8x2.6 smd paste-1000 mask-1000: 5(-2.1,-1.35) 7(2.1,-1.35)
  round 1.813 smd paste-1000 mask-1000: 6(-0.034,0.943)
  rrect40% 0.25x0.7 smd paste+0 mask-1000: 12(0.825,2.6) 13(0.325,2.6) 14(-0.175,2.6) 15(-0.675,2.6) 16(-1.175,2.6)
  Top Layer region: -1.45,1.85 -1.437,1.9 -1.4,1.937 -1.35,1.95 -1.35,1.95 0.9,1.95 0.938,1.942 0.971,1.921 0.992,1.888 1,1.85 1,1.85 1,-2.9 0.987,-2.95 0.95,-2.987 0.9,-3 0.9,-3 -0.9,-3 -0.95,-2.987 -0.987,-2.95 -1,-2.9 -1,-2.9 -1,0.585 -1.004,0.604 -1.015,0.62 -1.031,0.631 -1.05,0.635 -1.05,0.635 -1.35,0.635 -1.388,0.643 -1.421,0.664 -1.442,0.697 -1.45,0.735 -1.45,0.735
  Top Layer region: 2.4,2.2 2.419,2.204 2.435,2.215 2.446,2.231 2.45,2.25 2.45,2.25 2.45,2.4 2.443,2.425 2.425,2.443 2.4,2.45 2.4,2.45 2.1,2.45 2.062,2.458 2.029,2.479 2.008,2.512 2,2.55 2,2.55 2,2.9 1.993,2.925 1.975,2.943 1.95,2.95 1.95,2.95 1.8,2.95 1.775,2.943 1.757,2.925 1.75,2.9 1.75,2.9 1.75,2.25 1.754,2.231 1.765,2.215 1.781,2.204 1.8,2.2 1.8,2.2
  Top Layer region: -2.4,2.2 -2.419,2.204 -2.435,2.215 -2.446,2.231 -2.45,2.25 -2.45,2.25 -2.45,2.4 -2.443,2.425 -2.425,2.443 -2.4,2.45 -2.4,2.45 -2.1,2.45 -2.062,2.458 -2.029,2.479 -2.008,2.512 -2,2.55 -2,2.55 -2,2.9 -1.993,2.925 -1.975,2.943 -1.95,2.95 -1.95,2.95 -1.8,2.95 -1.781,2.946 -1.765,2.935 -1.754,2.919 -1.75,2.9 -1.75,2.9 -1.75,2.25 -1.754,2.231 -1.765,2.215 -1.781,2.204 -1.8,2.2 -1.8,2.2
  silkscreen extent -3.17,-3.1 2.65,3.1, body extent -2.6,-3.1 2.6,3.05, height 0.25
SIL0010D-MFG [mm]
  rrect40% 0.65x0.25 smd paste+0 mask+0: 1(-0.625,1) 2(-0.625,0.5) 3(-0.625,0) 4(-0.625,-0.5) 5(-0.625,-1) 6(0.625,-1) 7(0.625,-0.5) 8(0.625,0) 9(0.625,0.5) 10(0.625,1)
  silkscreen extent -1.77,-1.53 1.05,1.53, body extent -1.15,-1.4 1.15,1.4, height 0.25
SMA [mm] "Molded Diode, 2-Leads, Body 4.3x2.6mm, IPC Medium Density, based on OnSemi component dimensions and land pattern"
  rect 2x2 smd: 1(-2,0) 2(2,0)
  silkscreen extent -3.66,-1.57 2.79,1.57, body extent -2.6,-1.3 2.6,1.3, height 2.42
SOD-523 [mm] "NXP Semiconductor recommended land pattern, nominal STEP model"
  rect 0.8x0.6 smd paste-0.05: 1(-0.55,0) 2(0.55,0)
  silkscreen extent -1.65,-0.66 1.2,0.66, body extent -0.8,-0.4 0.8,0.4, height 0.72
WE-LHMI_4020 [mm] "WERTH"
  rrect7% 1.5x2.4 smd: 1(-1.85,0) 2(1.85,0)
  silkscreen extent -2.2,-2.2 2.2,2.2, body extent -2.15,-2.15 2.15,2.15, height 2
WEEE_Minimum [mil] "WEEElie bin"
  silkscreen extent -95,-172 99,104
WL-SMCW_GREEN [mm] "WURTH"
  rect 0.8x0.8 smd: 1(-0.8,0) 2(0.8,0)
  silkscreen extent -1.9,-0.8 1.2,0.8, body extent -0.85,-0.45 0.85,0.45, height 0.8

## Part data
2: library part CMP-0074844-1
4: library part CMP-0074847-1, "FCC_disclaimer"
5: library part CMP-0074769-3, Manufacturer="Texas Instruments"
6 7 8: library part CMP-0074837-1, "IEC 61010-1 Hot Surface Warning"
9: library part CMP-0003616-3
10: library part CMP-0077236-1
11: library part CMP-0077237-1
12: library part CMP-0077238-1
C1 C2 C3 C4 C5 C6 C7: library part CMP-0096021-1, "10 µF ±10% 100V Ceramic Capacitor X7R 1210 (3225 Metric)", Digikey Part Number=445-C3225X7R2A106K250ACCT-ND, Manufacturer=TDK, Mouser Part Number=810-C3225X7R2A106K25, Operating Temperature Range="-55°C to +125°C", Tempco=15%, Temperature Characteristic=X7R, Tolerance_%=10%, ValueDisplayed=10uF
C8 C9 C10 C15 C16 C17 C32 C33 C34: library part CMP-0750059-1, "CAP, CERM, 1 µF, 100 V,+/- 10%, X7S, 0805", Cap_Case=0805, Manufacturer=TDK, Tempco=X7S, Tolerance_%=10%, Value2=100V, ValueDisplayed=1µF
C11 C14 C35: library part CMP-0006302-2, "CAP, CERM, 2.2 uF, 10 V, +/- 10%, X7S, 0402", Cap_Case=0402_065, Manufacturer=TDK, Supplier Part Number 1=445-9097-1-ND, Tempco=X7S, Tolerance_%=10%, Value1="0.005925 ohm", Value2=10V, ValueDisplayed=2.2uF
C12 C20 C24 C25 C26 C27 C37 C41 C45 C49 C55 C56 C59 C93: "CAP, CERM, 0.1 uF, 16 V, +/- 10%, X7R, 0402", Cap_Case=0402, Manufacturer=MuRata, PartNumber=GCM155R71C104KA55D, Supplier Part Number 1=490-4759-2-ND, Tempco=X7R, Tolerance_%=10%, Value1=Unknown, Value2=16V, ValueDisplayed=0.1uF
C13 C18 C19 C21 C22 C23 C36 C38 C39: library part CMP-0077894-3, "CAP, CERM, 0.22 µF, 100 V,+/- 10%, X7S, AEC-Q200 Grade 1, 0603", Cap_Case=0603, Manufacturer="Taiyo Yuden", Supplier Part Number 1=587-5012-1-ND, Tempco=X7S, Tolerance_%=10%, Value2=100V, ValueDisplayed=0.22µF
C28 C29 C30 C31 C42 C43: "CAP, CERM, 47 pF, 25 V, +/- 5%, C0G/NP0, 0402", Cap_Case=0402, Manufacturer=MuRata, PartNumber=GRM1555C1E470JA01D, Supplier Part Number 1=81-GRM1555C1E470JA1D, Tempco=C0G/NP0, Tolerance_%=5%, Value1=Unknown, Value2=25V, ValueDisplayed=47pF
C40 C57: library part CMP-0006527-2, "CAP, CERM, 4.7 uF, 16 V, +/- 20%, X6T, 0402", Cap_Case=0402, Manufacturer=MuRata, Tempco=X6T, Tolerance_%=20%, Value1=Unknown, Value2=16V, ValueDisplayed=4.7uF
C44 C46 C52 C63: "CAP, CERM, 0.033 uF, 10 V, +/- 10%, X7R, 0402", Cap_Case=0402, Manufacturer=MuRata, PartNumber=GRM155R71A333KA01D, Supplier Part Number 1=490-1315-1-ND, Tempco=X7R, Tolerance_%=10%, Value1=Unknown, Value2=10V, ValueDisplayed=0.033uF
C47 C53 C60: "CAP, CERM, 1500 pF, 25 V, +/- 5%, C0G/NP0, 0402", Cap_Case=0402, Manufacturer=Kemet, PartNumber=C0402H152J3GAC7867, Supplier Part Number 1=399-6291-1-ND, Tempco=C0G/NP0, Tolerance_%=5%, Value1=Unknown, Value2=25V, ValueDisplayed=1500pF
C48 C51 C54: "CAP, CERM, 0.1 uF, 16 V, +/- 10%, X7R, 0603", Cap_Case=0603, Manufacturer=MuRata, PartNumber=GRM188R71C104KA01D, Supplier Part Number 1=490-1532-1-ND, Tempco=X7R, Tolerance_%=10%, Value1=Unknown, Value2=16V, ValueDisplayed=0.1uF
C50: library part CMP-0007317-5, "CAP, CERM, 1 uF, 10 V, +/- 10%, X5R, 0603", Cap_Case=0603, Manufacturer=MuRata, Supplier Part Number 1=490-1543-1-ND, Tempco=X5R, Tolerance_%=10%, Value1=Unknown, Value2=10V, ValueDisplayed=1uF
C58: library part CMP-0006594-2, "CAP, CERM, 2.2 uF, 16 V, +/- 10%, X5R, 0402", Cap_Case=0402, Manufacturer=MuRata, Supplier Part Number 1=490-10695-1-ND, Tempco=X5R, Tolerance_%=10%, Value1=Unknown, Value2=16V, ValueDisplayed=2.2uF
C61: library part CMP-0006943-4, "CAP, CERM, 4700 pF, 50 V, +/- 10%, X7R, 0603", Cap_Case=0603, Manufacturer=Kemet, Supplier Part Number 1=399-1087-1-ND, Tempco=X7R, Tolerance_%=10%, Value1=Unknown, Value2=50V, ValueDisplayed=4700pF
C62: library part CMP-0006919-4, "CAP, CERM, 33 pF, 50 V, +/- 5%, C0G/NP0, 0603", Cap_Case=0603, Manufacturer=Kemet, Supplier Part Number 1=399-1055-1-ND, Tempco=C0G/NP0, Tolerance_%=5%, Value1=Unknown, Value2=50V, ValueDisplayed=33pF
C64: library part CMP-0080092-1, "CAP, CERM, 1000 pF, 25 V,+/- 1%, C0G/NP0, 0603", Cap_Case=0603, Manufacturer=Kemet, Supplier Part Number 1=399-7825-1-ND, Tempco=C0G/NP0, Tolerance_%=1%, Value2=25V, ValueDisplayed=1000pF
C65 C66: library part CMP-0006711-2, "CAP, CERM, 470 pF, 100 V, +/- 10%, X7R, 0402", Cap_Case=0402, Manufacturer=MuRata, Supplier Part Number 1=GRM155R72A471KA01D-ND, Tempco=X7R, Tolerance_%=10%, Value1=Unknown, Value2=100V, ValueDisplayed=470pF
C67 C72 C76 C77: library part CMP-0006659-2, "CAP, CERM, 0.1 uF, 25 V, +/- 10%, X7R, 0402", Cap_Case=0402, Manufacturer=MuRata, Supplier Part Number 1=490-10698-1-ND, Tempco=X7R, Tolerance_%=10%, Value1=Unknown, Value2=25V, ValueDisplayed=0.1uF
C68 C69 C70 C71 C73 C74 C75: "CAP, CERM, 2200 pF, 16 V, +/- 10%, X7R, 0603", Cap_Case=0603, Manufacturer="Wurth Elektronik", PartNumber=885012206036, Supplier Part Number 1=710-885012206036, Tempco=X7R, Tolerance_%=10%, Value1=Unknown, Value2=16V, ValueDisplayed=2200pF
C78: library part CMP-0006641-2, "CAP, CERM, 0.1 uF, 16 V, +/- 10%, X7R, 0402", Cap_Case=0402, Manufacturer=MuRata, Supplier Part Number 1=490-3261-1-ND, Tempco=X7R, Tolerance_%=10%, Value1=Unknown, Value2=16V, ValueDisplayed=0.1uF
C79: library part CMP-0006247-2, "CAP, CERM, 18 pF, 50 V, +/- 5%, C0G/NP0, 0402", Cap_Case=0402, Manufacturer=TDK, Supplier Part Number 1=445-1238-1-ND, Tempco=C0G/NP0, Tolerance_%=5%, Value1=Unknown, Value2=50V, ValueDisplayed=18pF
C80: library part CMP-0009135-2, "CAP, CERM, 4.7 uF, 100 V, +/- 10%, X7S, 1210", Cap_Case=1210, Manufacturer=TDK, Supplier Part Number 1=445-8912-1-ND, Tempco=X7S, Tolerance_%=10%, Value1=Unknown, Value2=100V, ValueDisplayed=4.7uF
C81: library part CMP-0007059-4, "CAP, CERM, 0.1 uF, 100 V, +/- 10%, X7S, 0603", Cap_Case=0603, Manufacturer=TDK, Supplier Part Number 1=445-5201-1-ND, Tempco=X7S, Tolerance_%=10%, Value1="0.04959 ohm", Value2=100V, ValueDisplayed=0.1uF
C82 C92: library part CMP-0007851-1, "CAP, CERM, 15 uF, 16 V, +/- 20%, X6S, 0805", Cap_Case=0805, Manufacturer=TDK, Supplier Part Number 1=445-14485-1-ND, Tempco=X6S, Tolerance_%=20%, Value1="0.001669 ohm", Value2=16V, ValueDisplayed=15uF
C83 C91: library part CMP-0007878-2, "CAP, CERM, 2.2 uF, 50 V, +/- 20%, X7R, 0805", Cap_Case=0805, Manufacturer=TDK, Supplier Part Number 1=445-5969-1-ND, Tempco=X7R, Tolerance_%=20%, Value1=Unknown, Value2=50V, ValueDisplayed=2.2uF
C84: library part CMP-0860562-1, "CAP, CERM, 0.01 µF, 50 V,+/- 10%, X7R, 0402", Cap_Case=0402, Manufacturer="Samsung Electro-Mechanics", Tempco=X7R, Tolerance_%=10%, Value2=50V, ValueDisplayed=0.01µF
C85: library part CMP-0007503-4, "CAP, CERM, 4.7 uF, 6.3 V, +/- 10%, X7R, 0603", Cap_Case=0603, Manufacturer="Taiyo Yuden", Tempco=X7R, Tolerance_%=10%, Value1=Unknown, Value2=6.3V, ValueDisplayed=4.7uF
C86 C88: library part CMP-0006360-2, "CAP, CERM, 470 pF, 50 V, +/- 10%, X7R, AEC-Q200 Grade 1, 0402", Cap_Case=0402, Manufacturer=MuRata, Supplier Part Number 1=490-4913-1-ND, Tempco=X7R, Tolerance_%=10%, Value1=Unknown, Value2=50V, ValueDisplayed=470pF
C87: library part CMP-0006416-2, "CAP, CERM, 120 pF, 50 V, +/- 1%, C0G/NP0, 0402", Cap_Case=0402, Manufacturer=MuRata, Supplier Part Number 1=490-8182-1-ND, Tempco=C0G/NP0, Tolerance_%=1%, Value1=Unknown, Value2=50V, ValueDisplayed=120pF
C89 C90: library part CMP-0007497-5, "CAP, CERM, 10 uF, 10 V, +/- 20%, X7R, 0603", Cap_Case=0603, Manufacturer=MuRata, Supplier Part Number 1=81-GRM188Z71A106MA3D, Tempco=X7R, Tolerance_%=20%, Value1=Unknown, Value2=10V, ValueDisplayed=10uF
D1: library part CMP-0029023-2, "Diode, Superfast Rectifier, 150 V, 1 A, SMA", Manufacturer="Diodes Inc.", PartNumber=ES1C-13-F, Value1=1A, Value2=0.92V
D2 D3 D4 D5 D6: "Diode, Schottky, 70 V, 0.07 A, SOD-523", Manufacturer=Nexperia, PartNumber=1PS79SB70,115, Value1=0.07A, Value2=0.41V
